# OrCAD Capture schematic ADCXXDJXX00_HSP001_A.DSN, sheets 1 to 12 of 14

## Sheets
1 PAGE01 - BLOCK DIAGRAM: title: BLOCK DIAGRAM; rev: A; note: HSP001
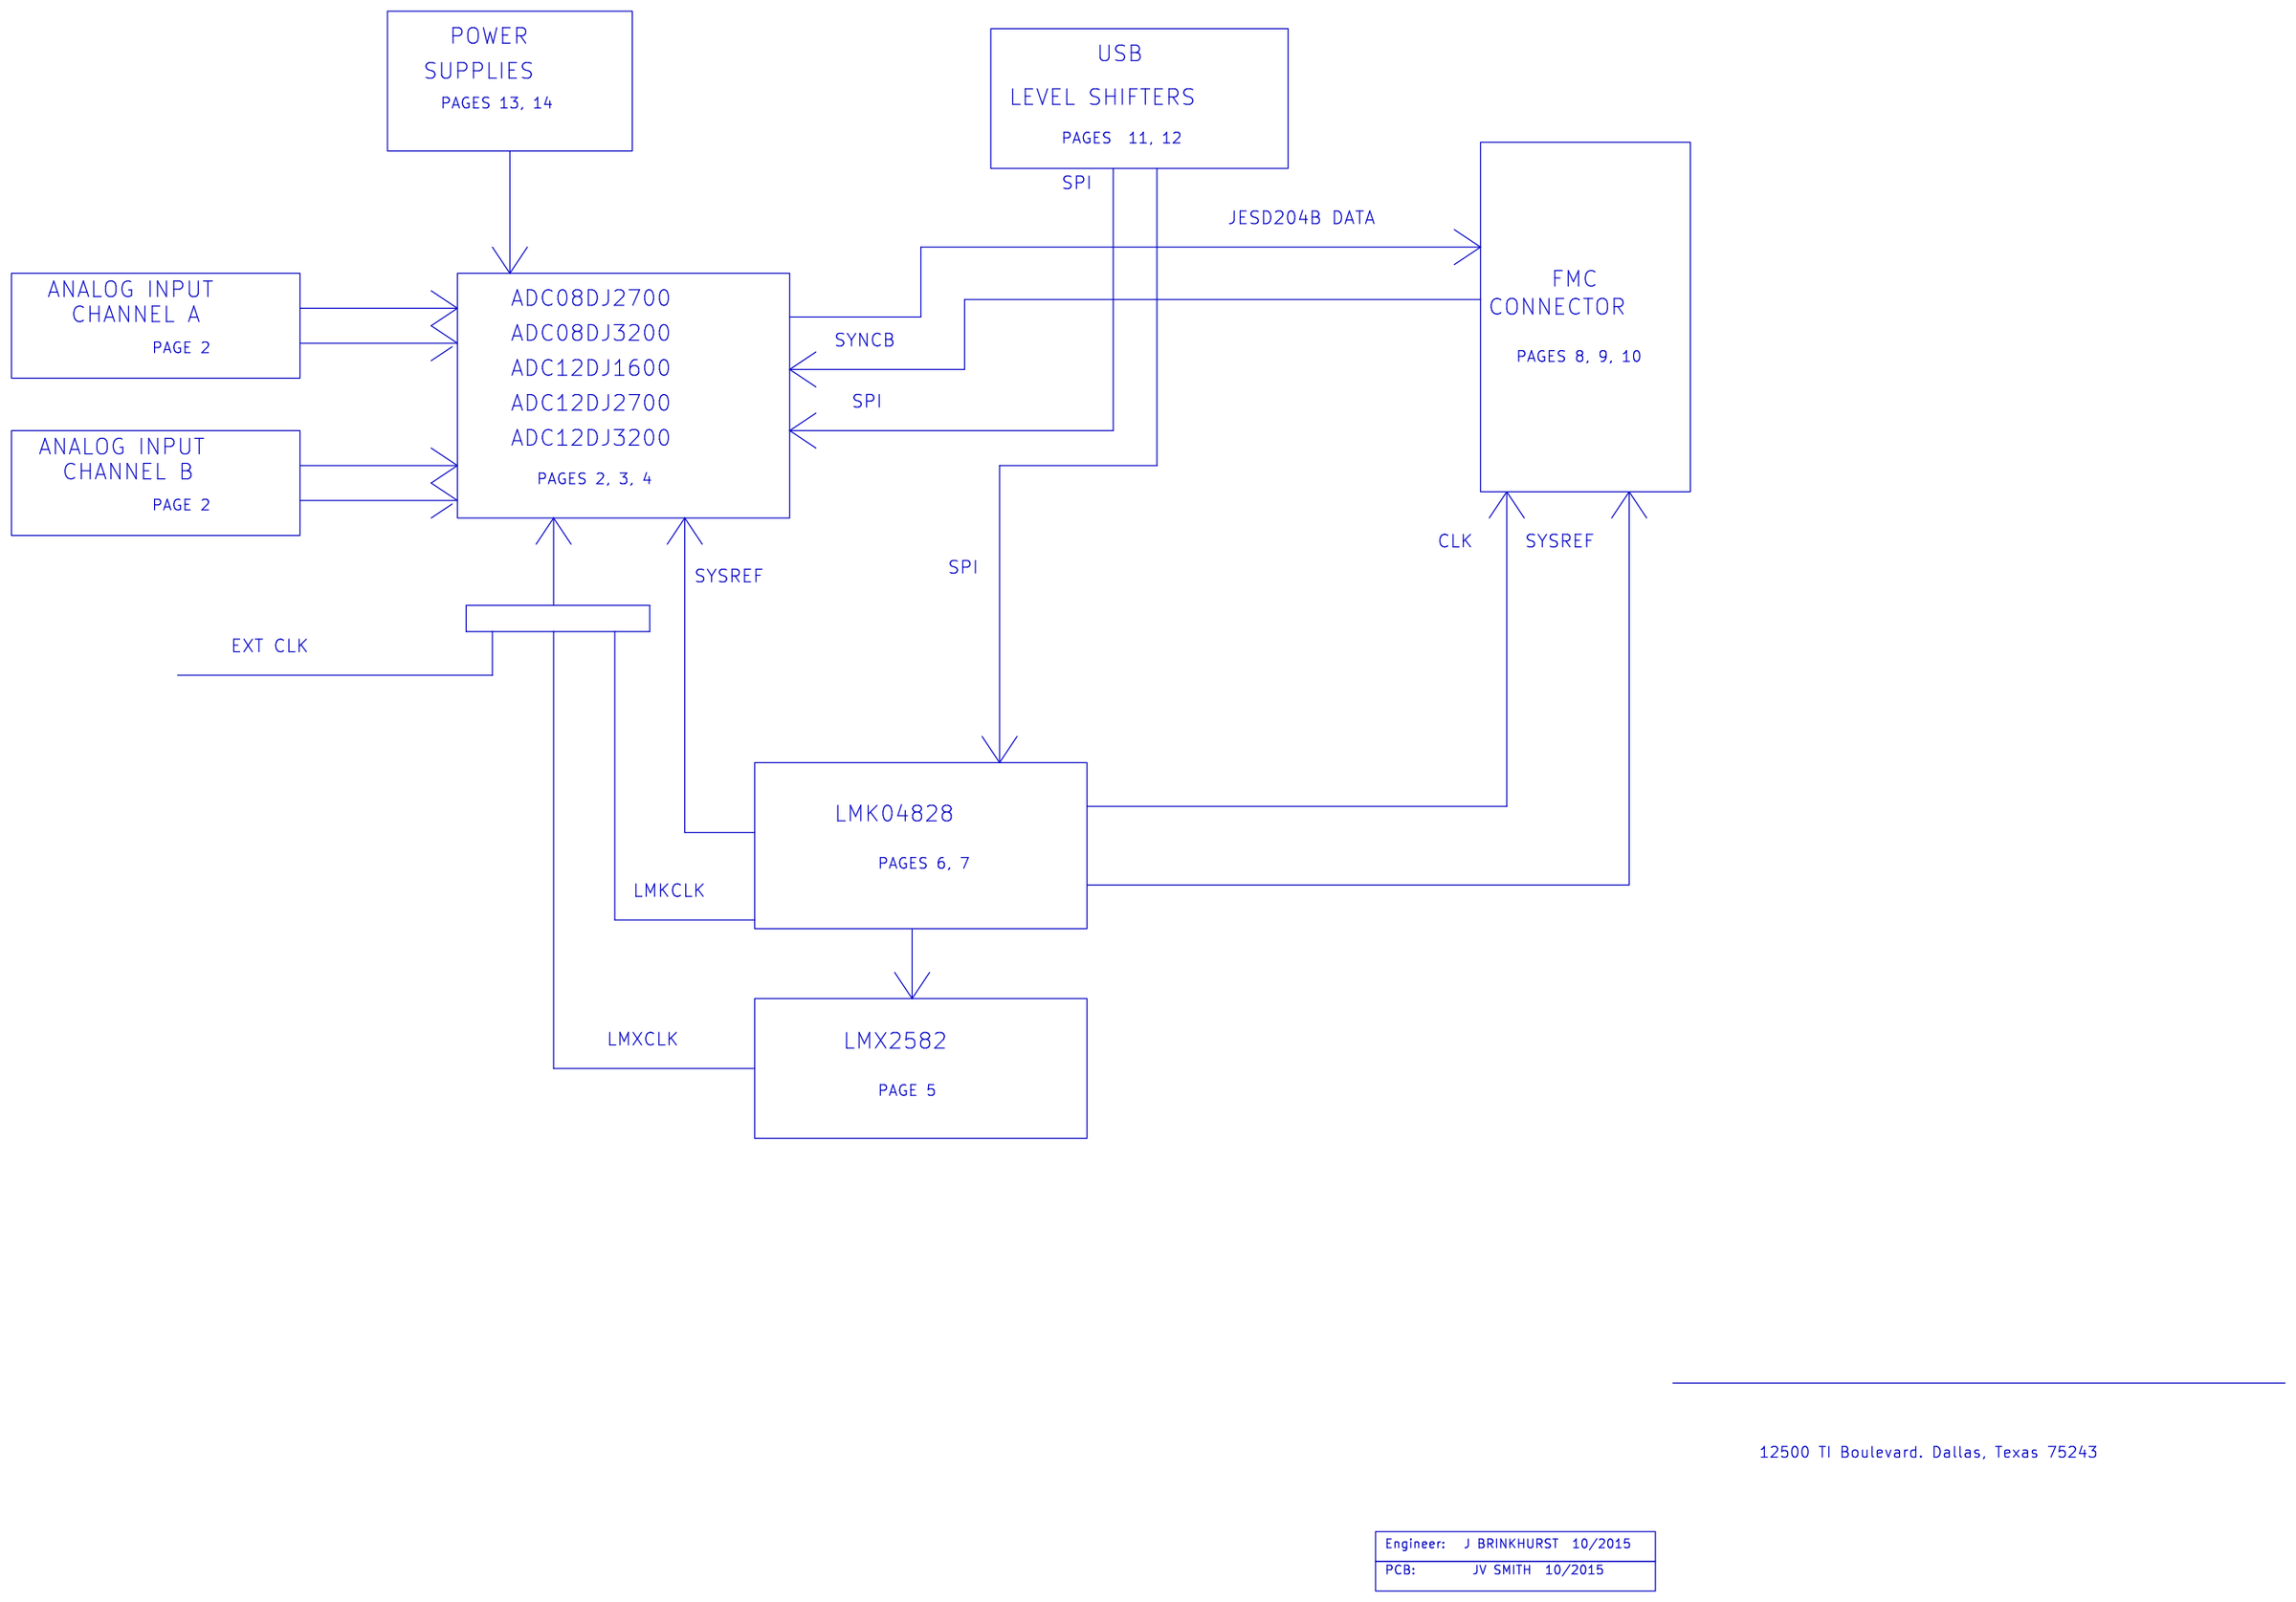
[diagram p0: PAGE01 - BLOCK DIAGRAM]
2 PAGE02 - ADC ANALOG INPUT: size B; title: ANALOG IN
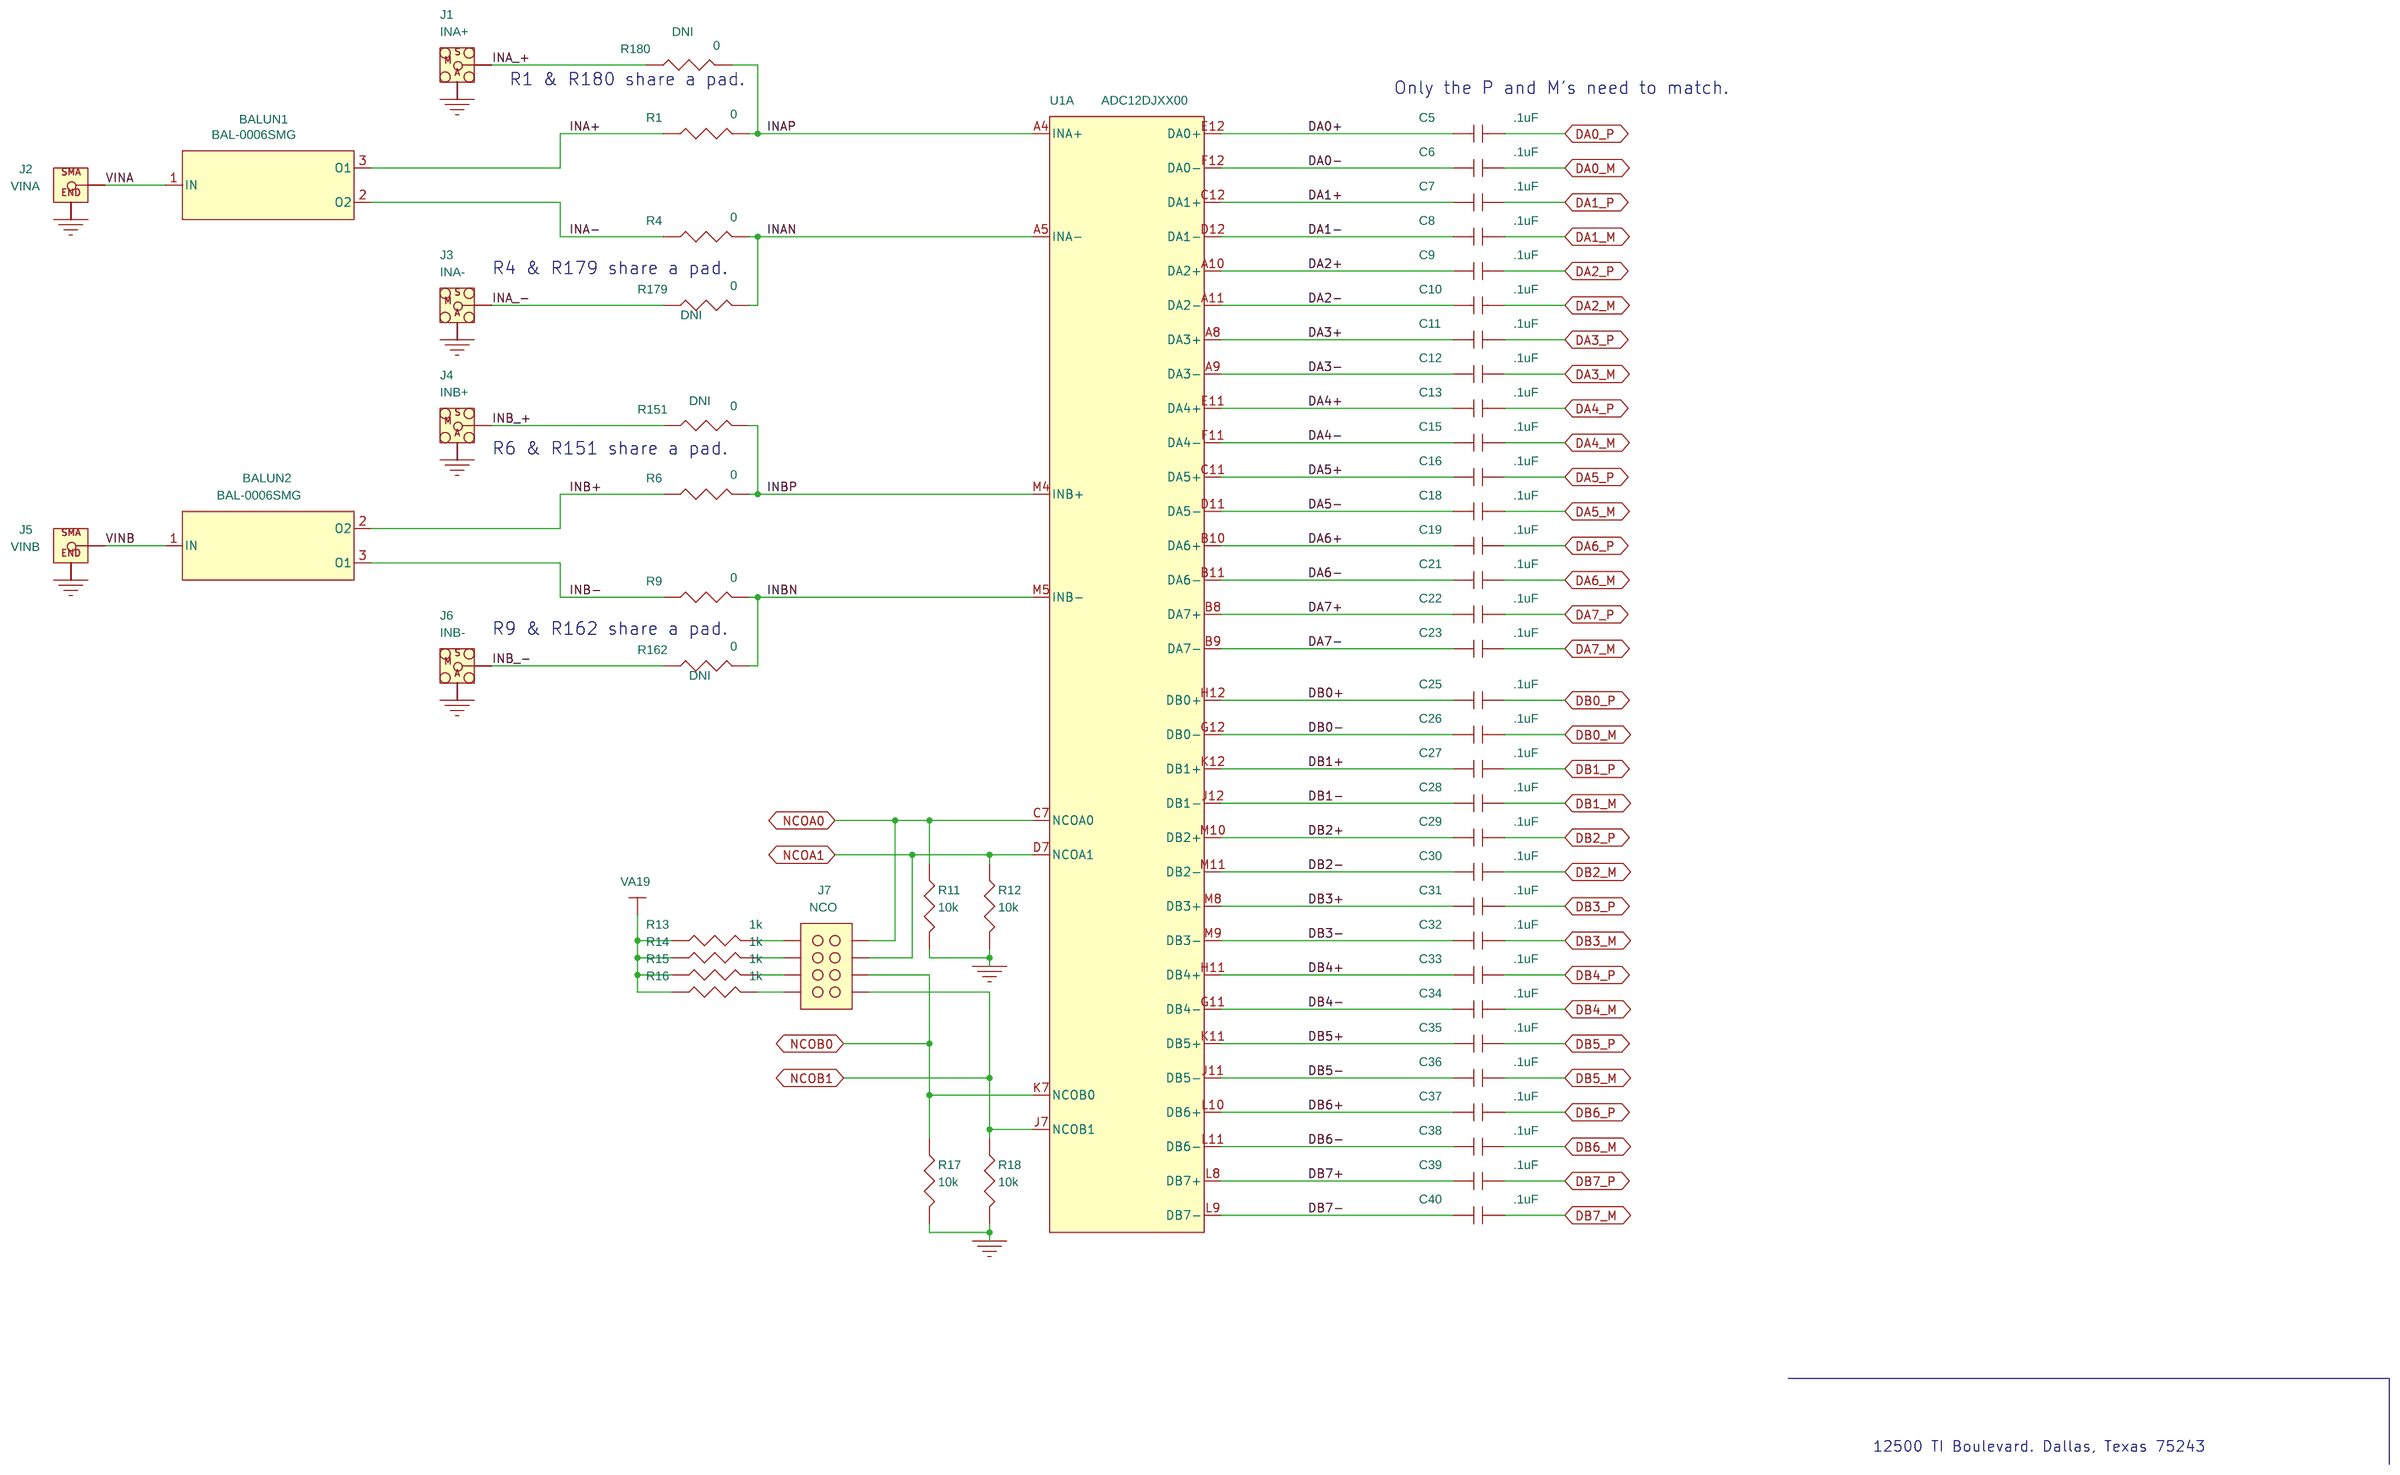
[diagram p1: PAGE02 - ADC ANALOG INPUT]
3 PAGE03 - ADC SPI: size B; title: ADC
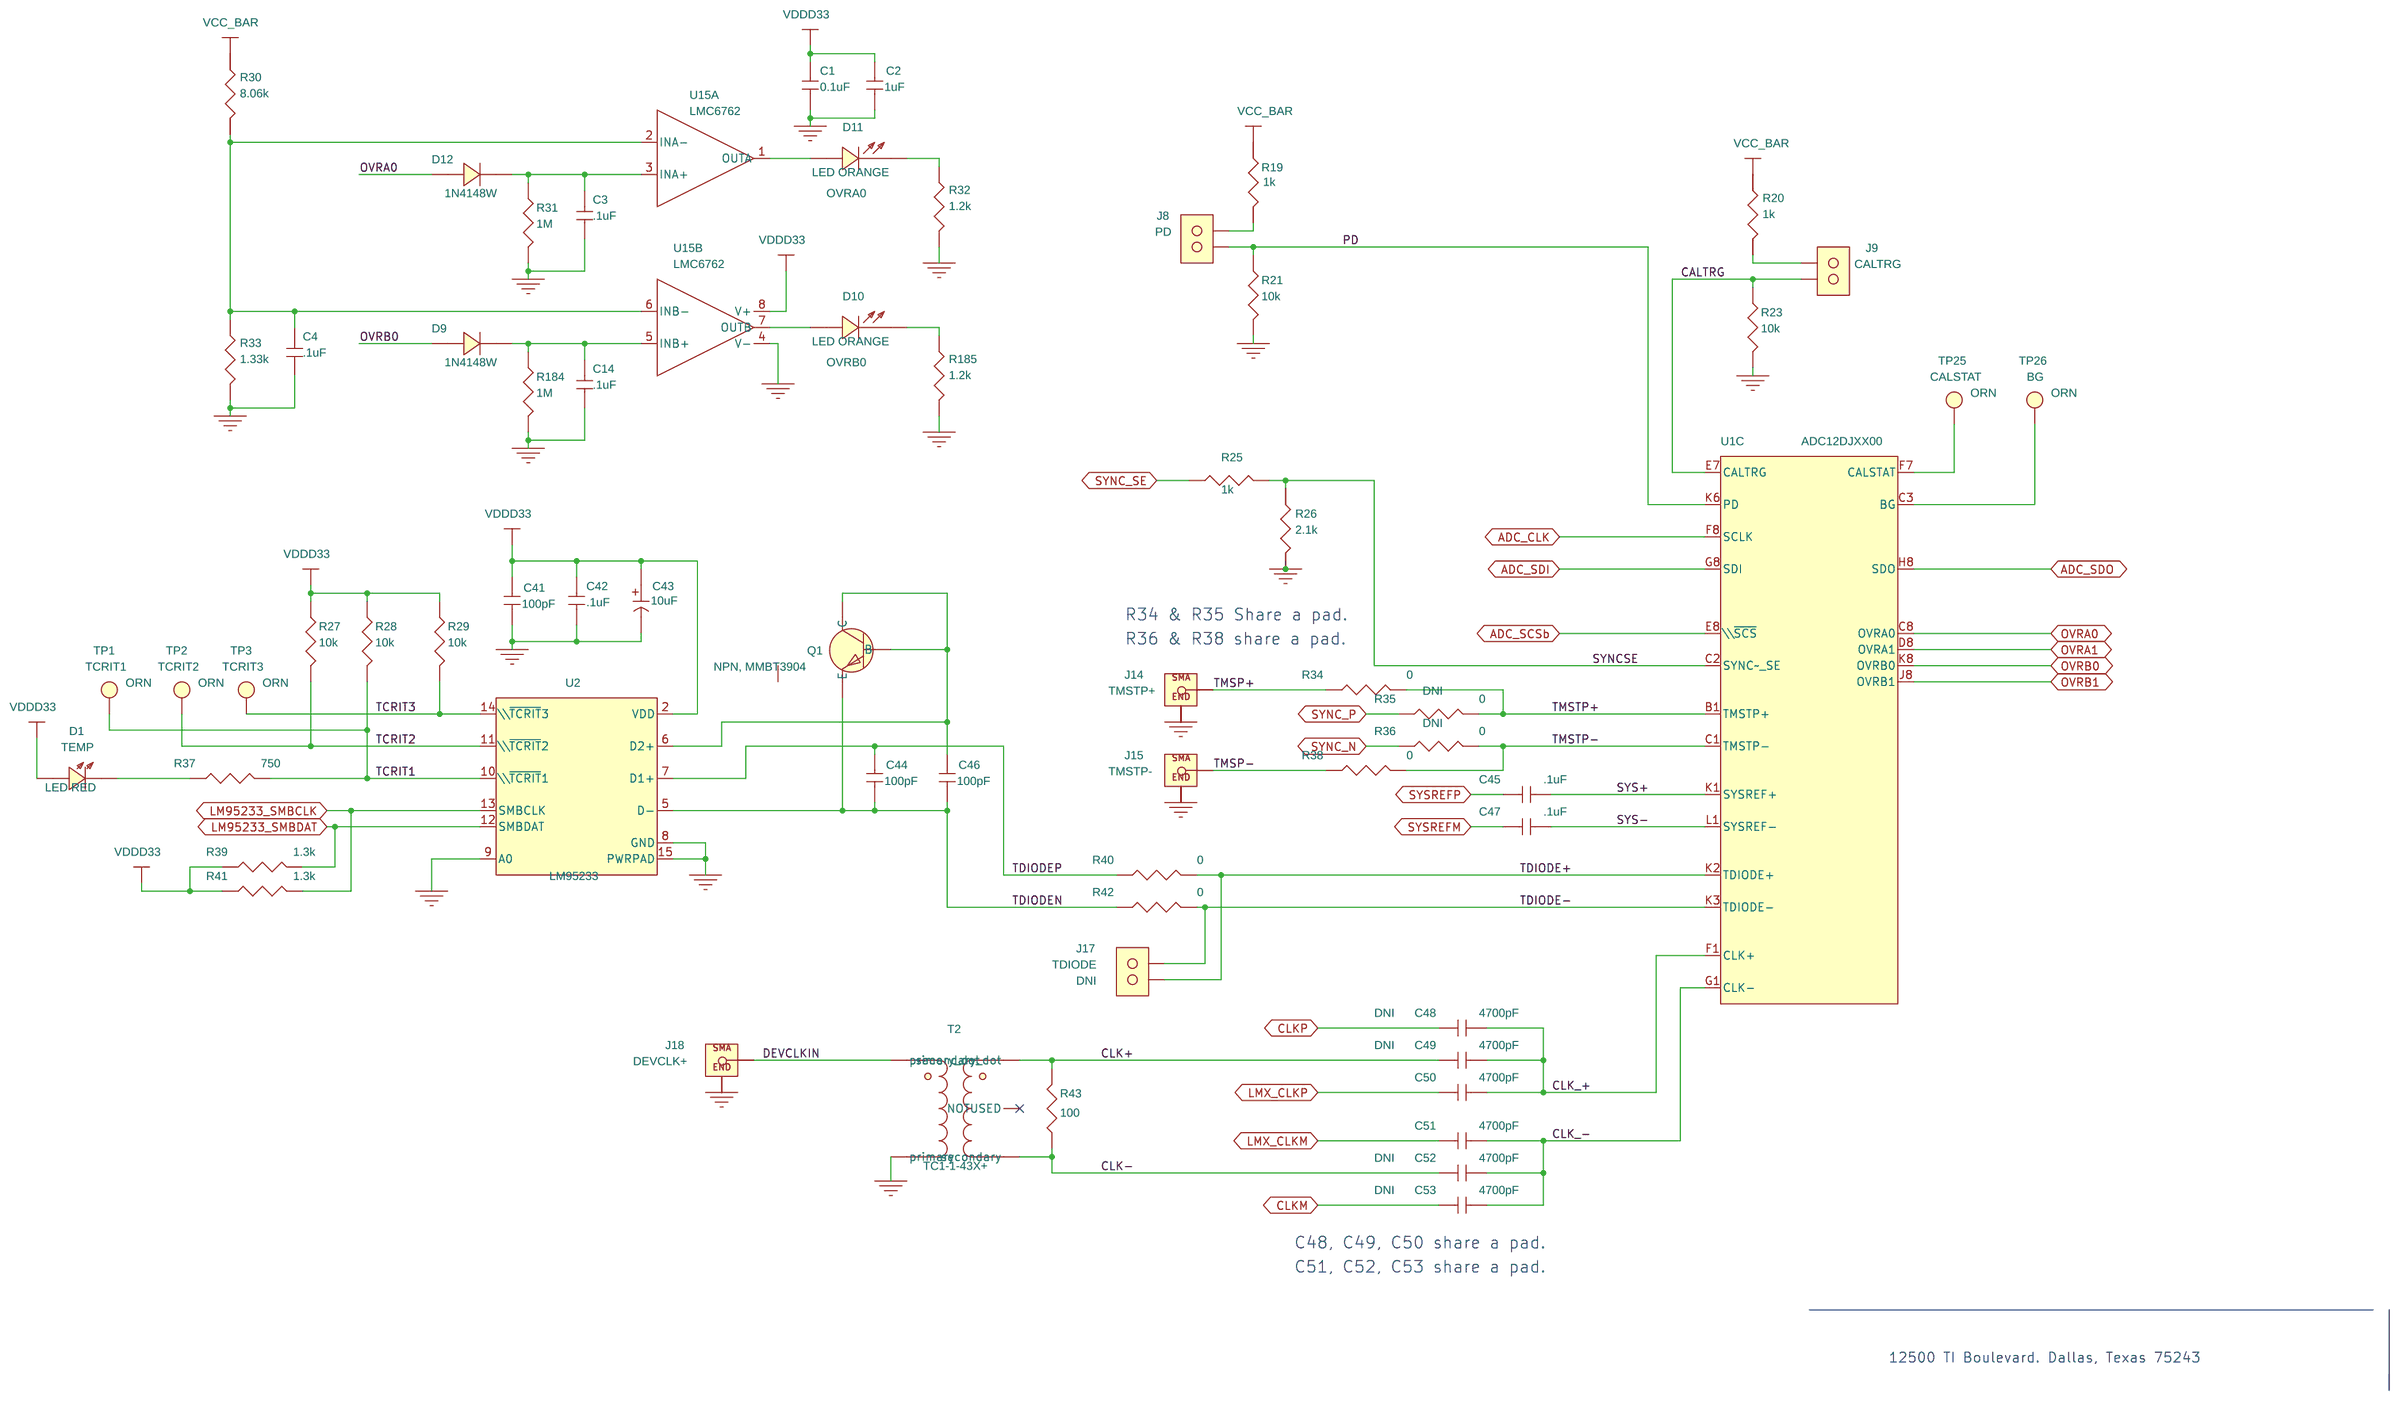
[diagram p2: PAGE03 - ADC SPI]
4 PAGE04 - ADC PWR: size B; title: ADC  POWER
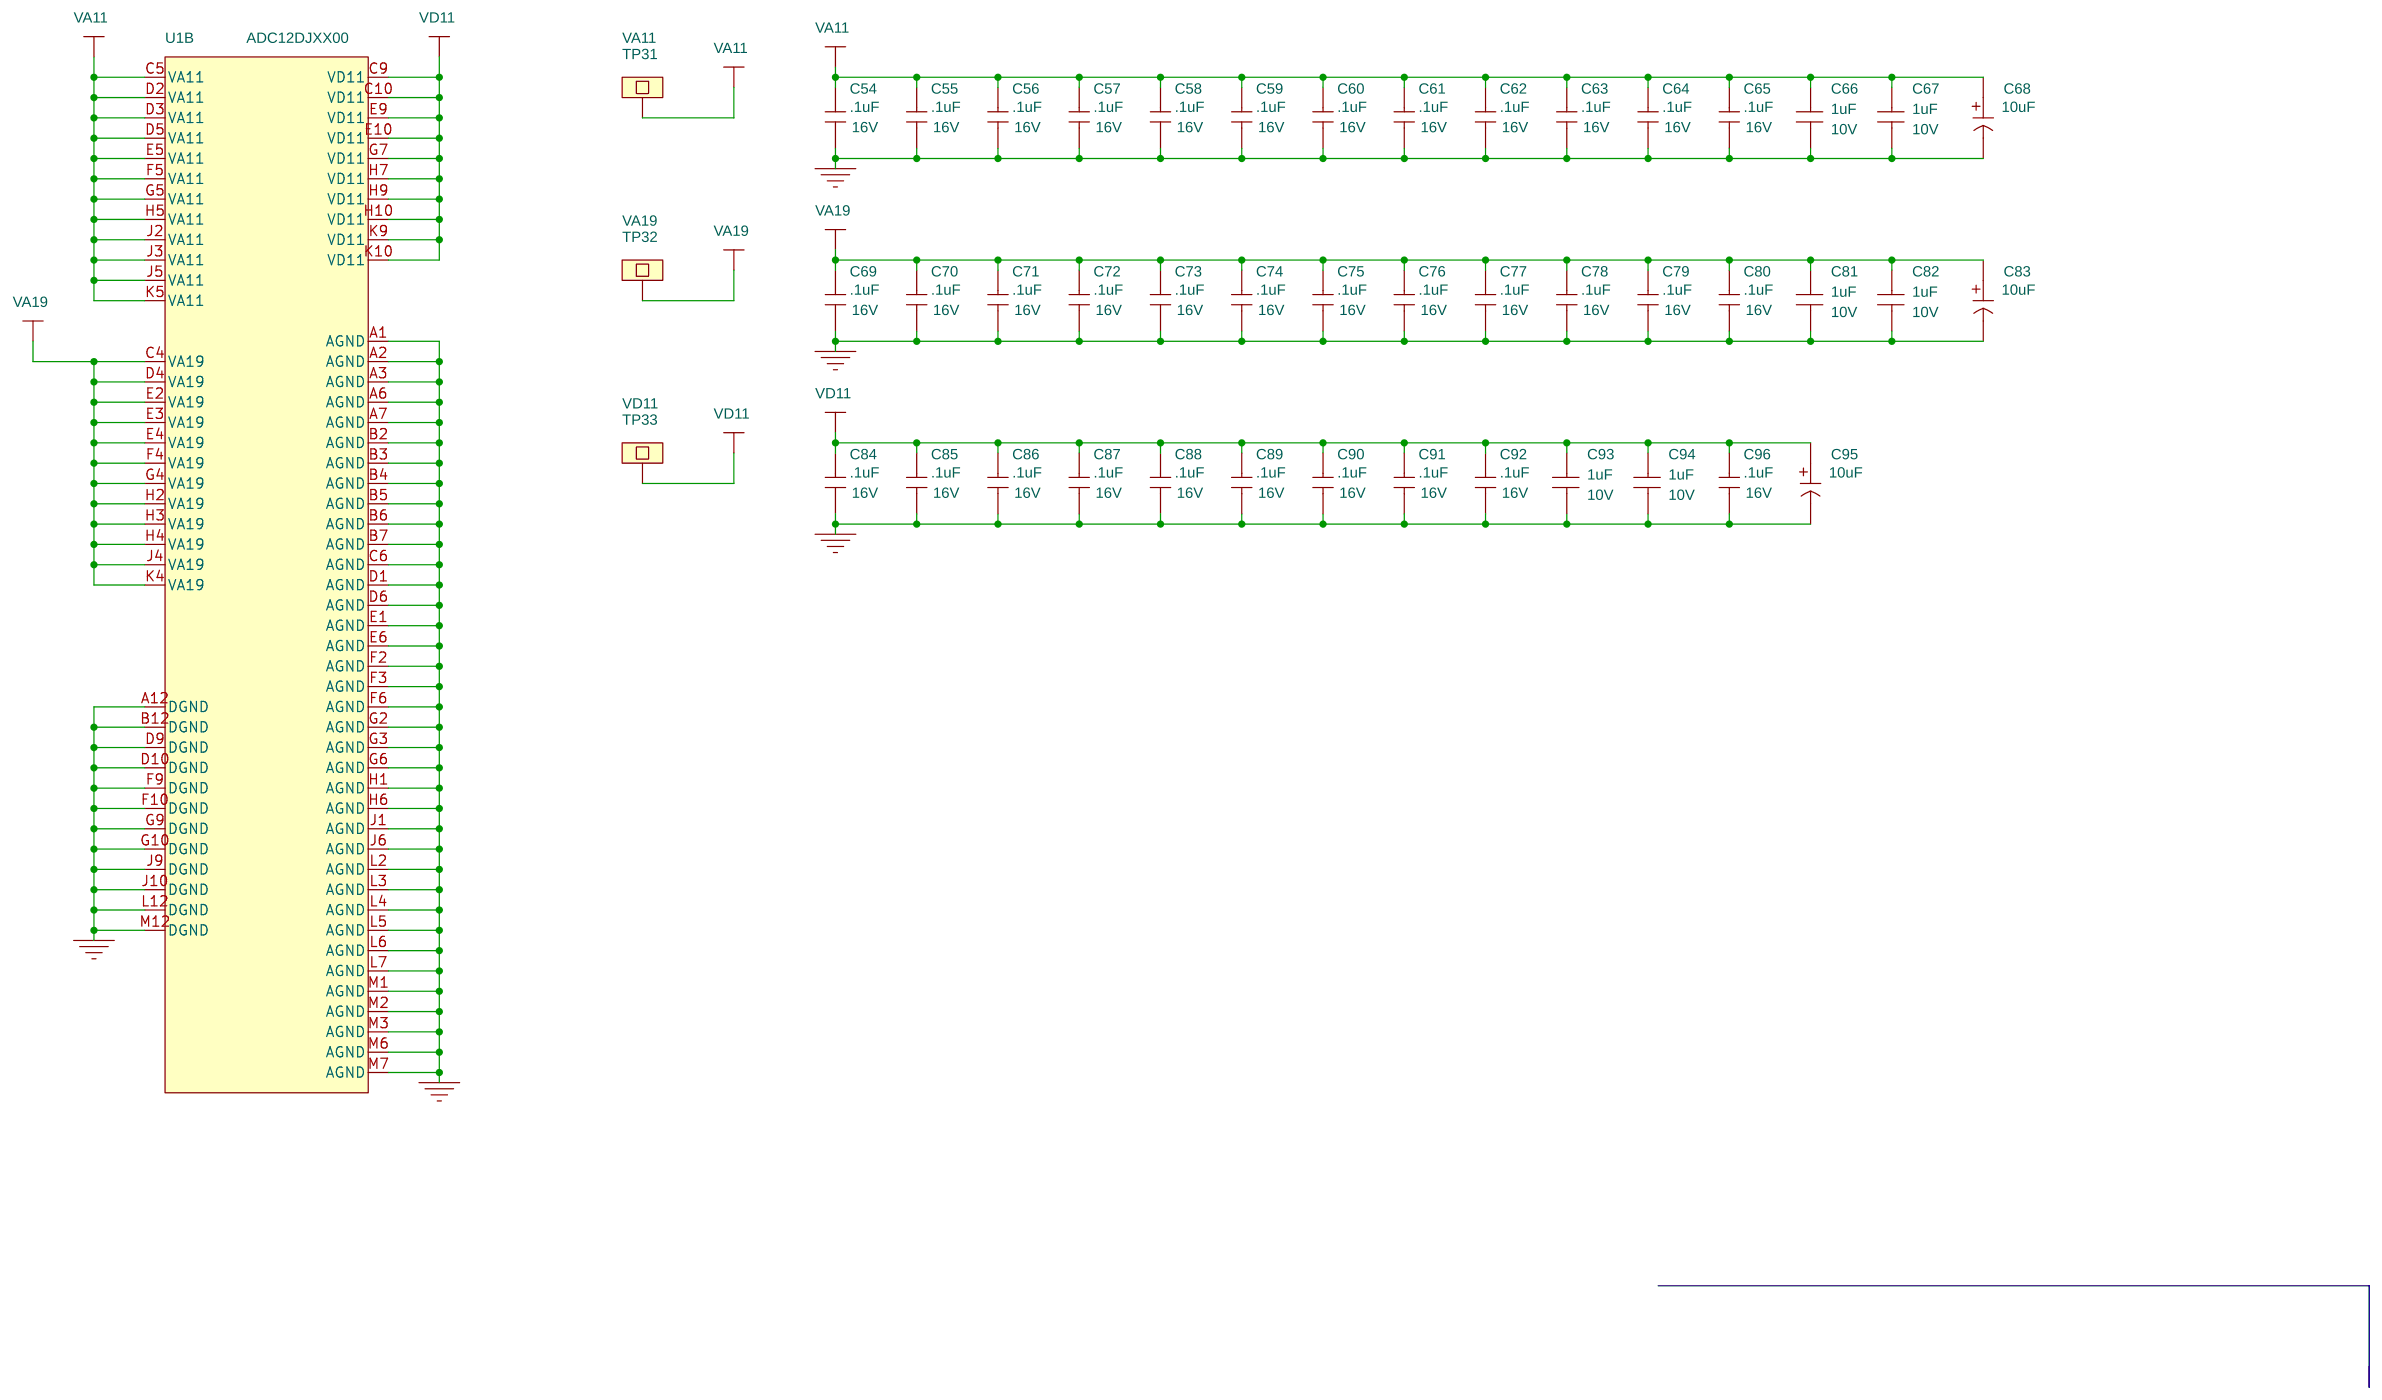
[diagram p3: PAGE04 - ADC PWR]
5 PAGE05 - LMX: size B; title: LMX
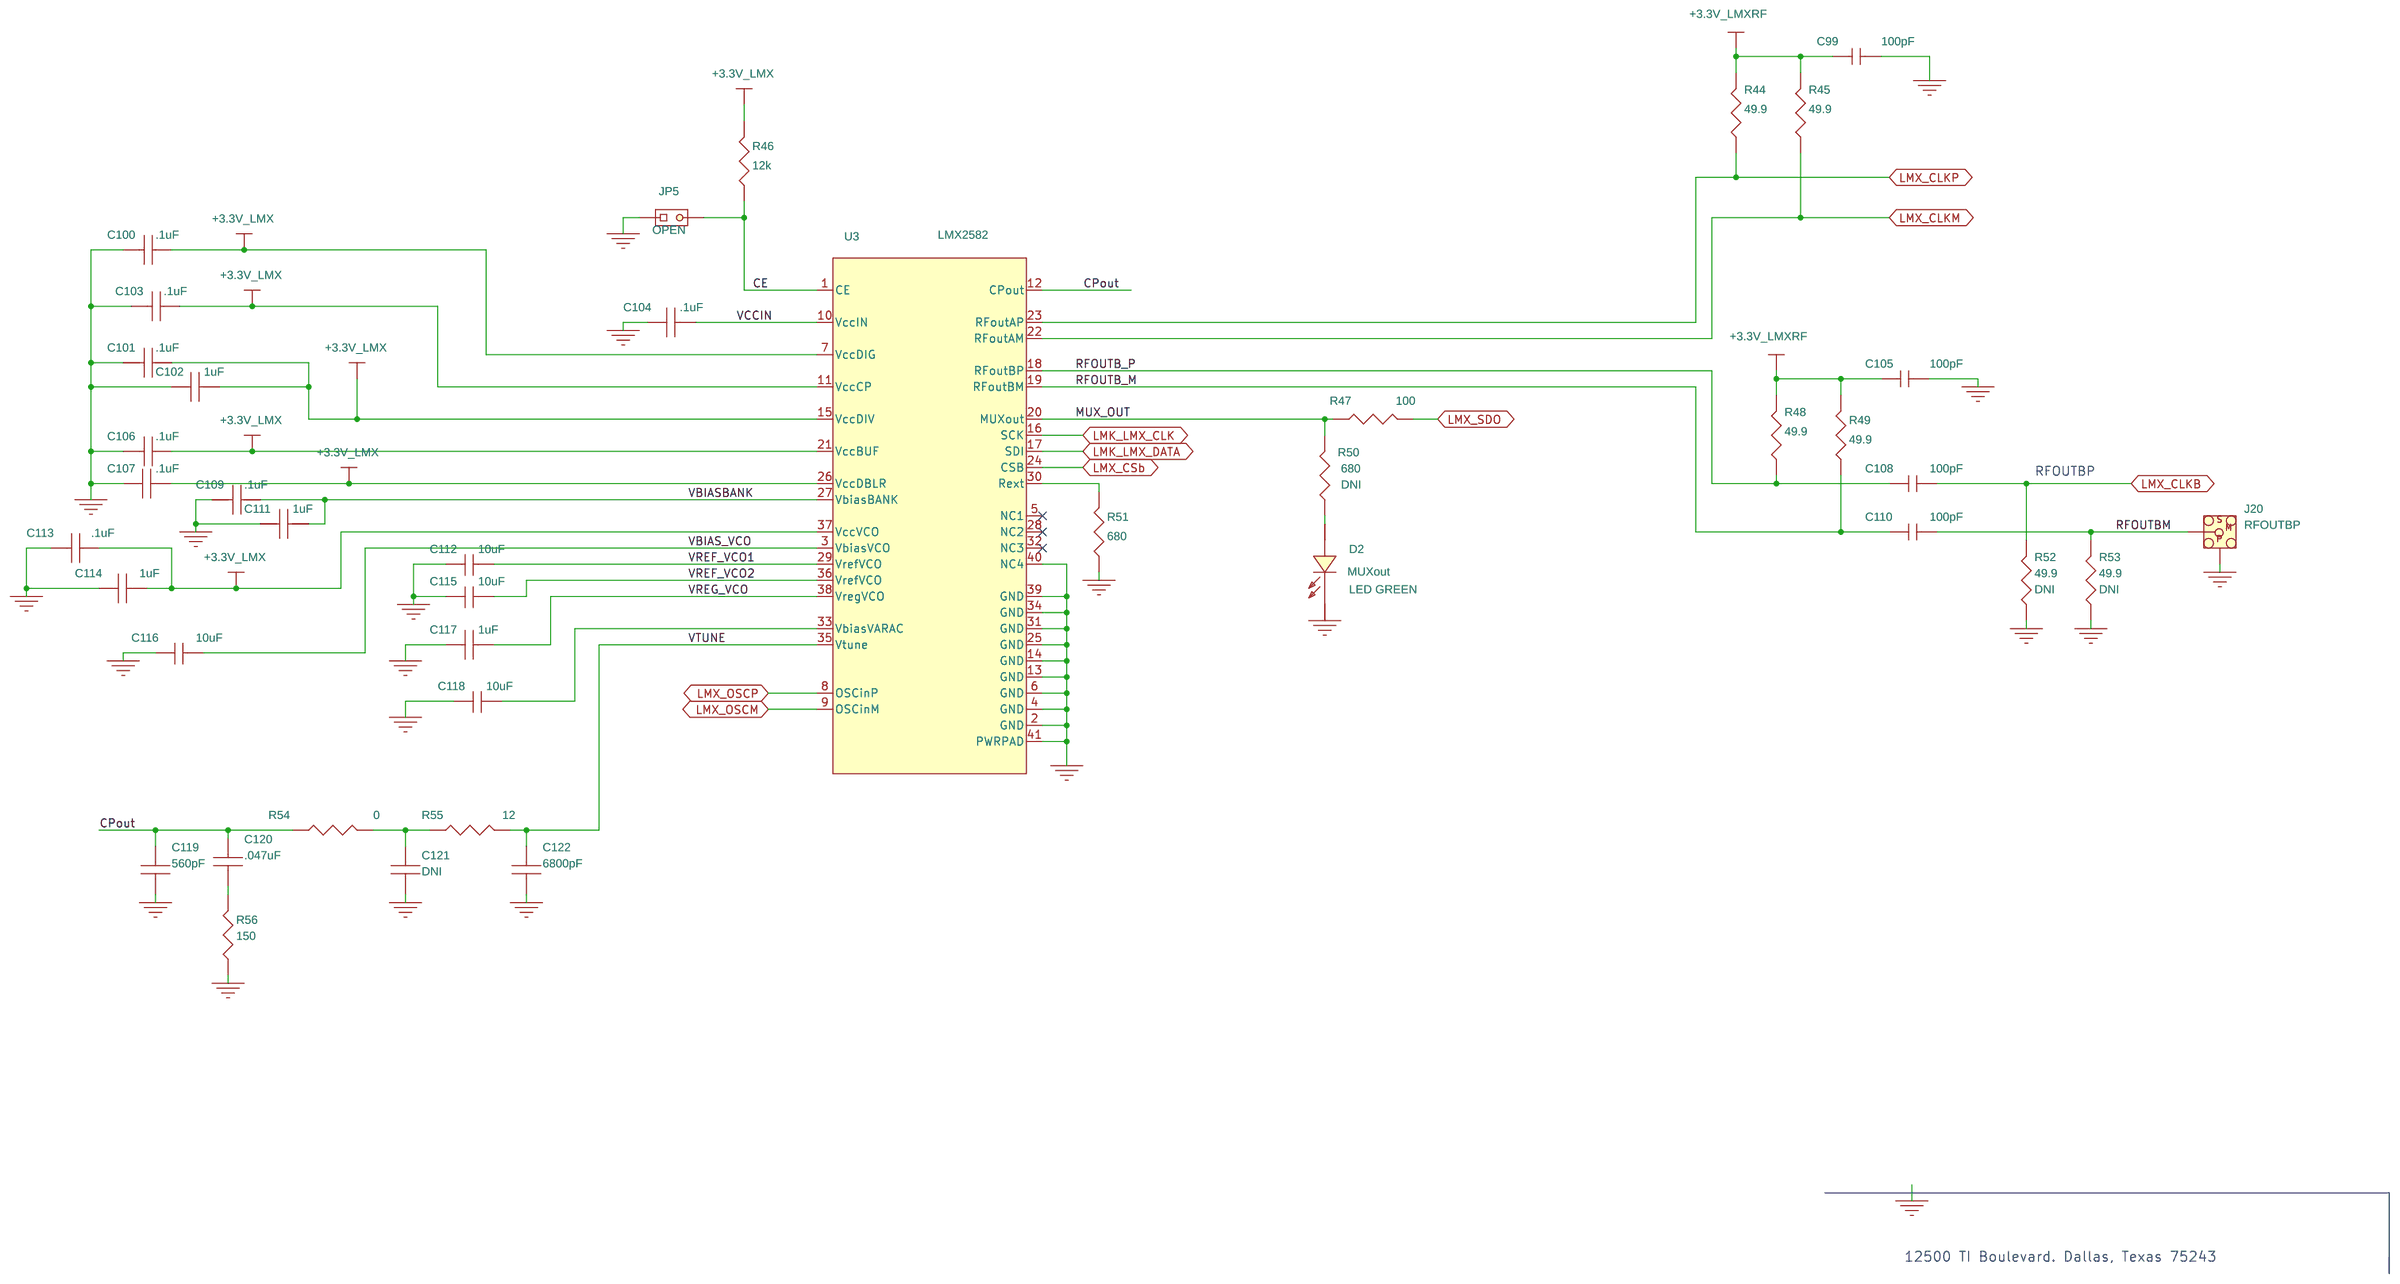
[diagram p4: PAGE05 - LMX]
6 PAGE06 - LMK: size B; title: LMK
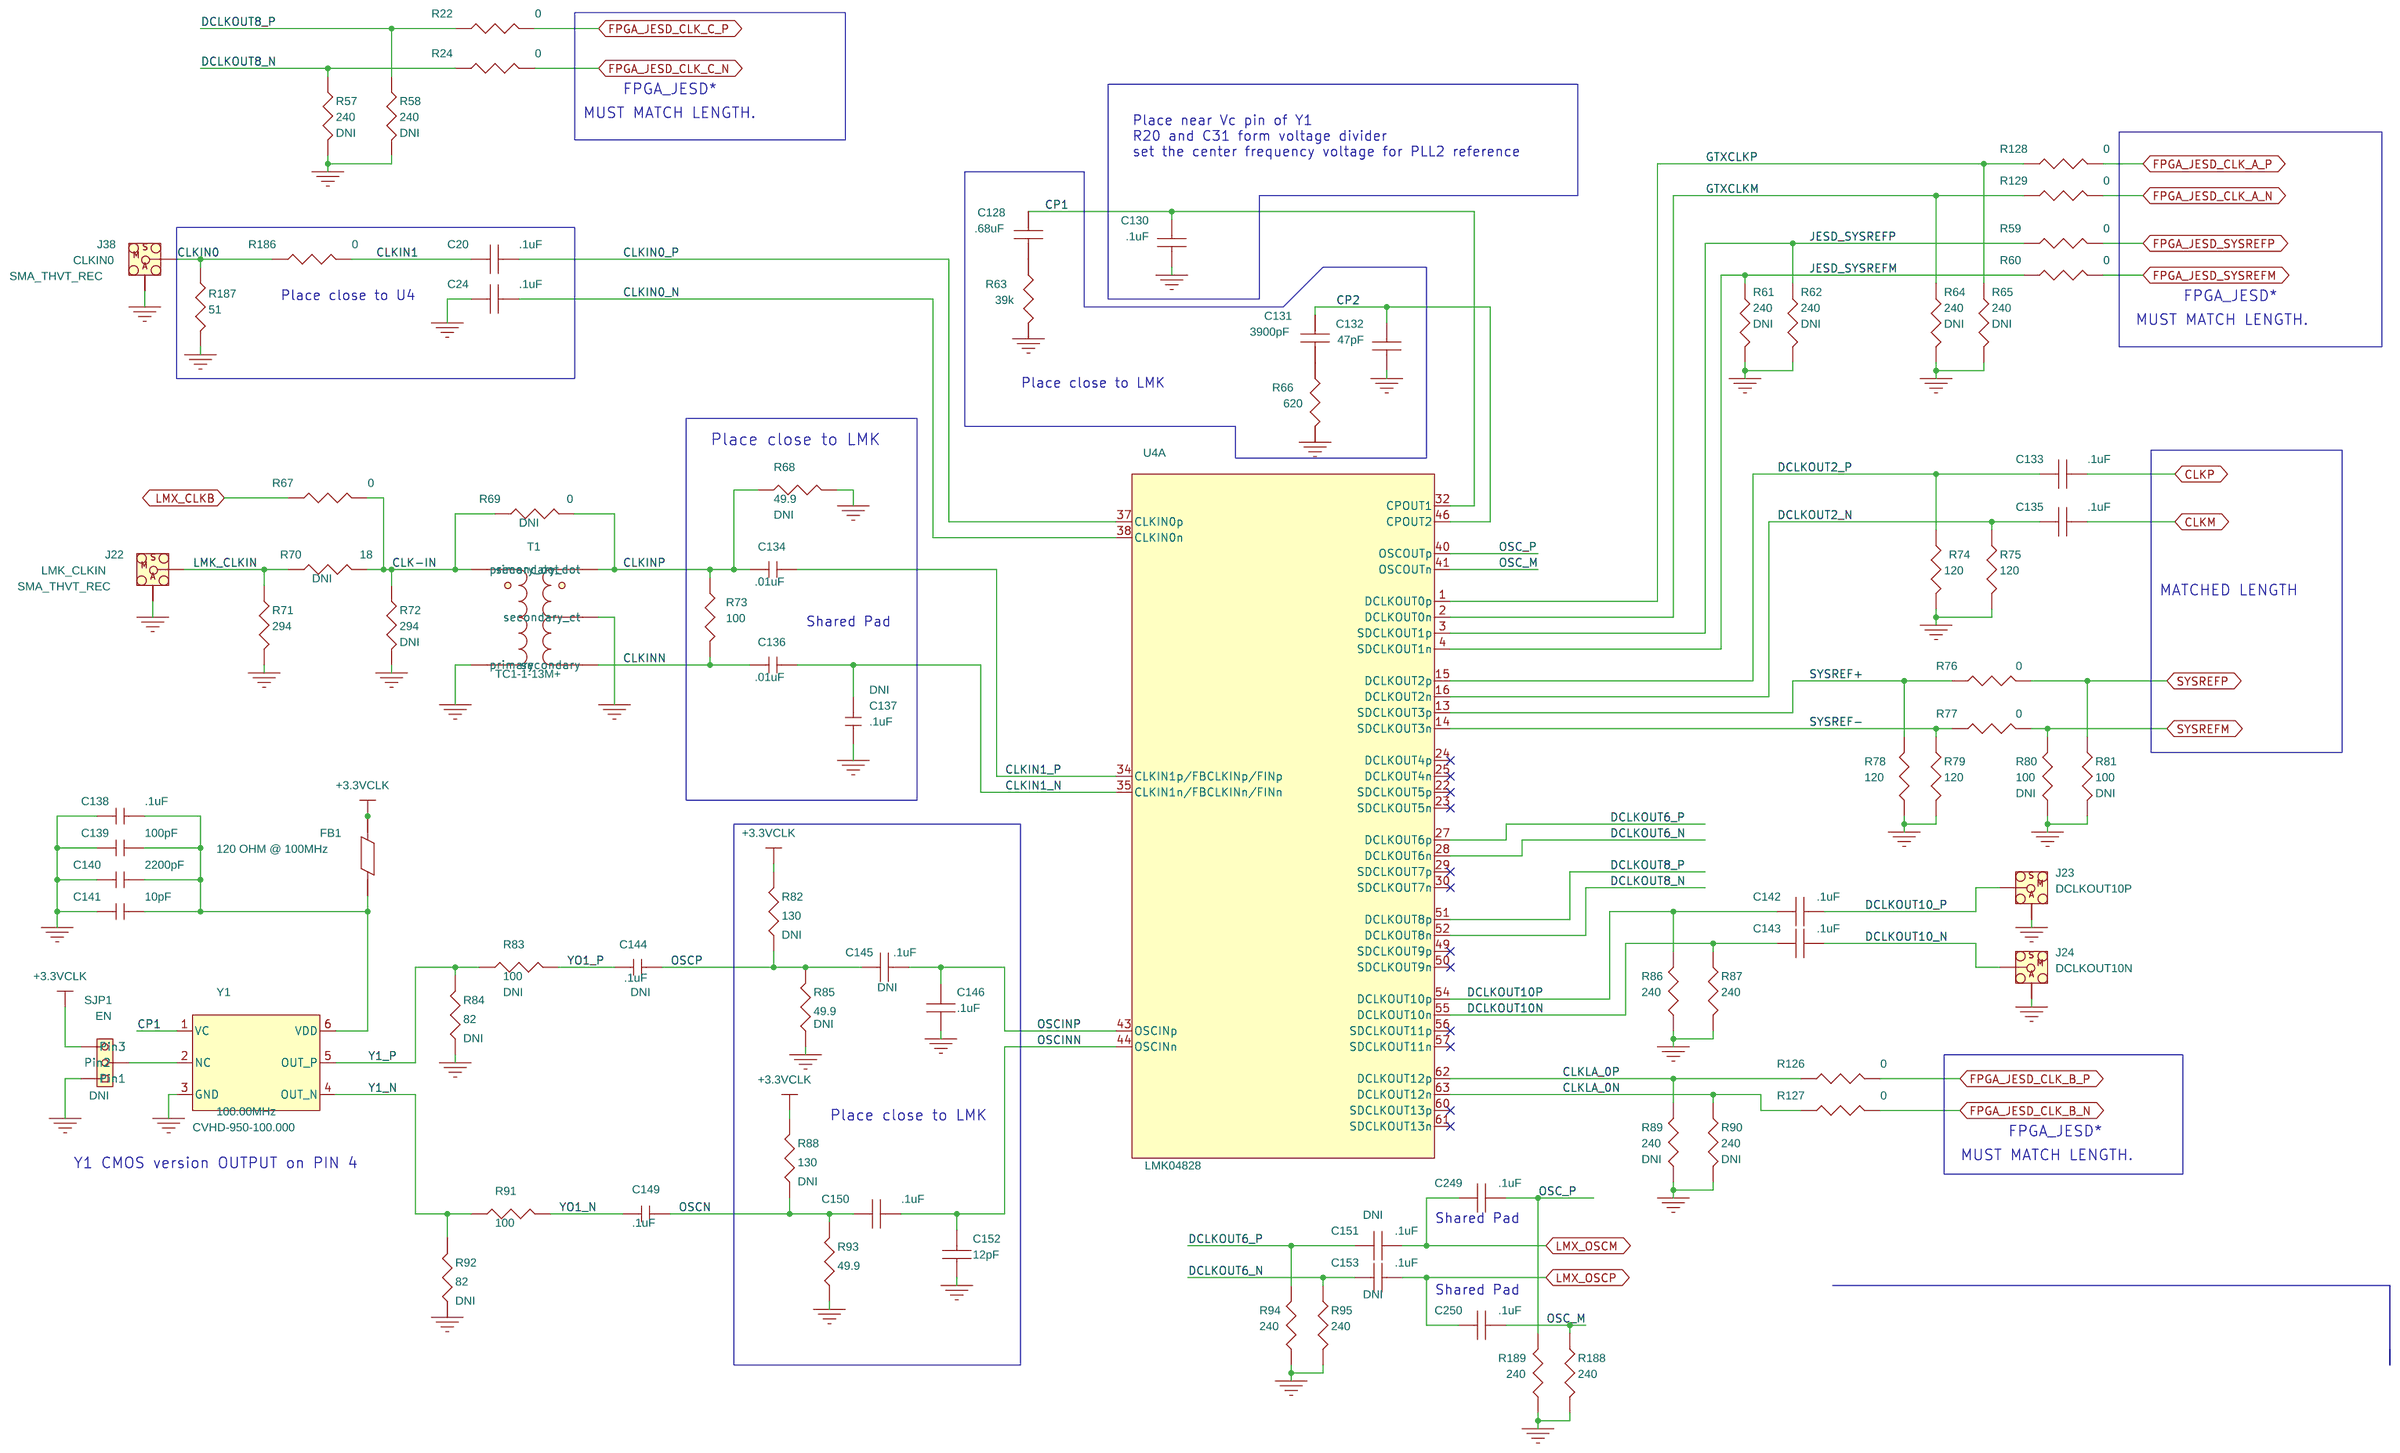
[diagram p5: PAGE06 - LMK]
7 PAGE07 - LMK POWER: size B; title: LMK POWER
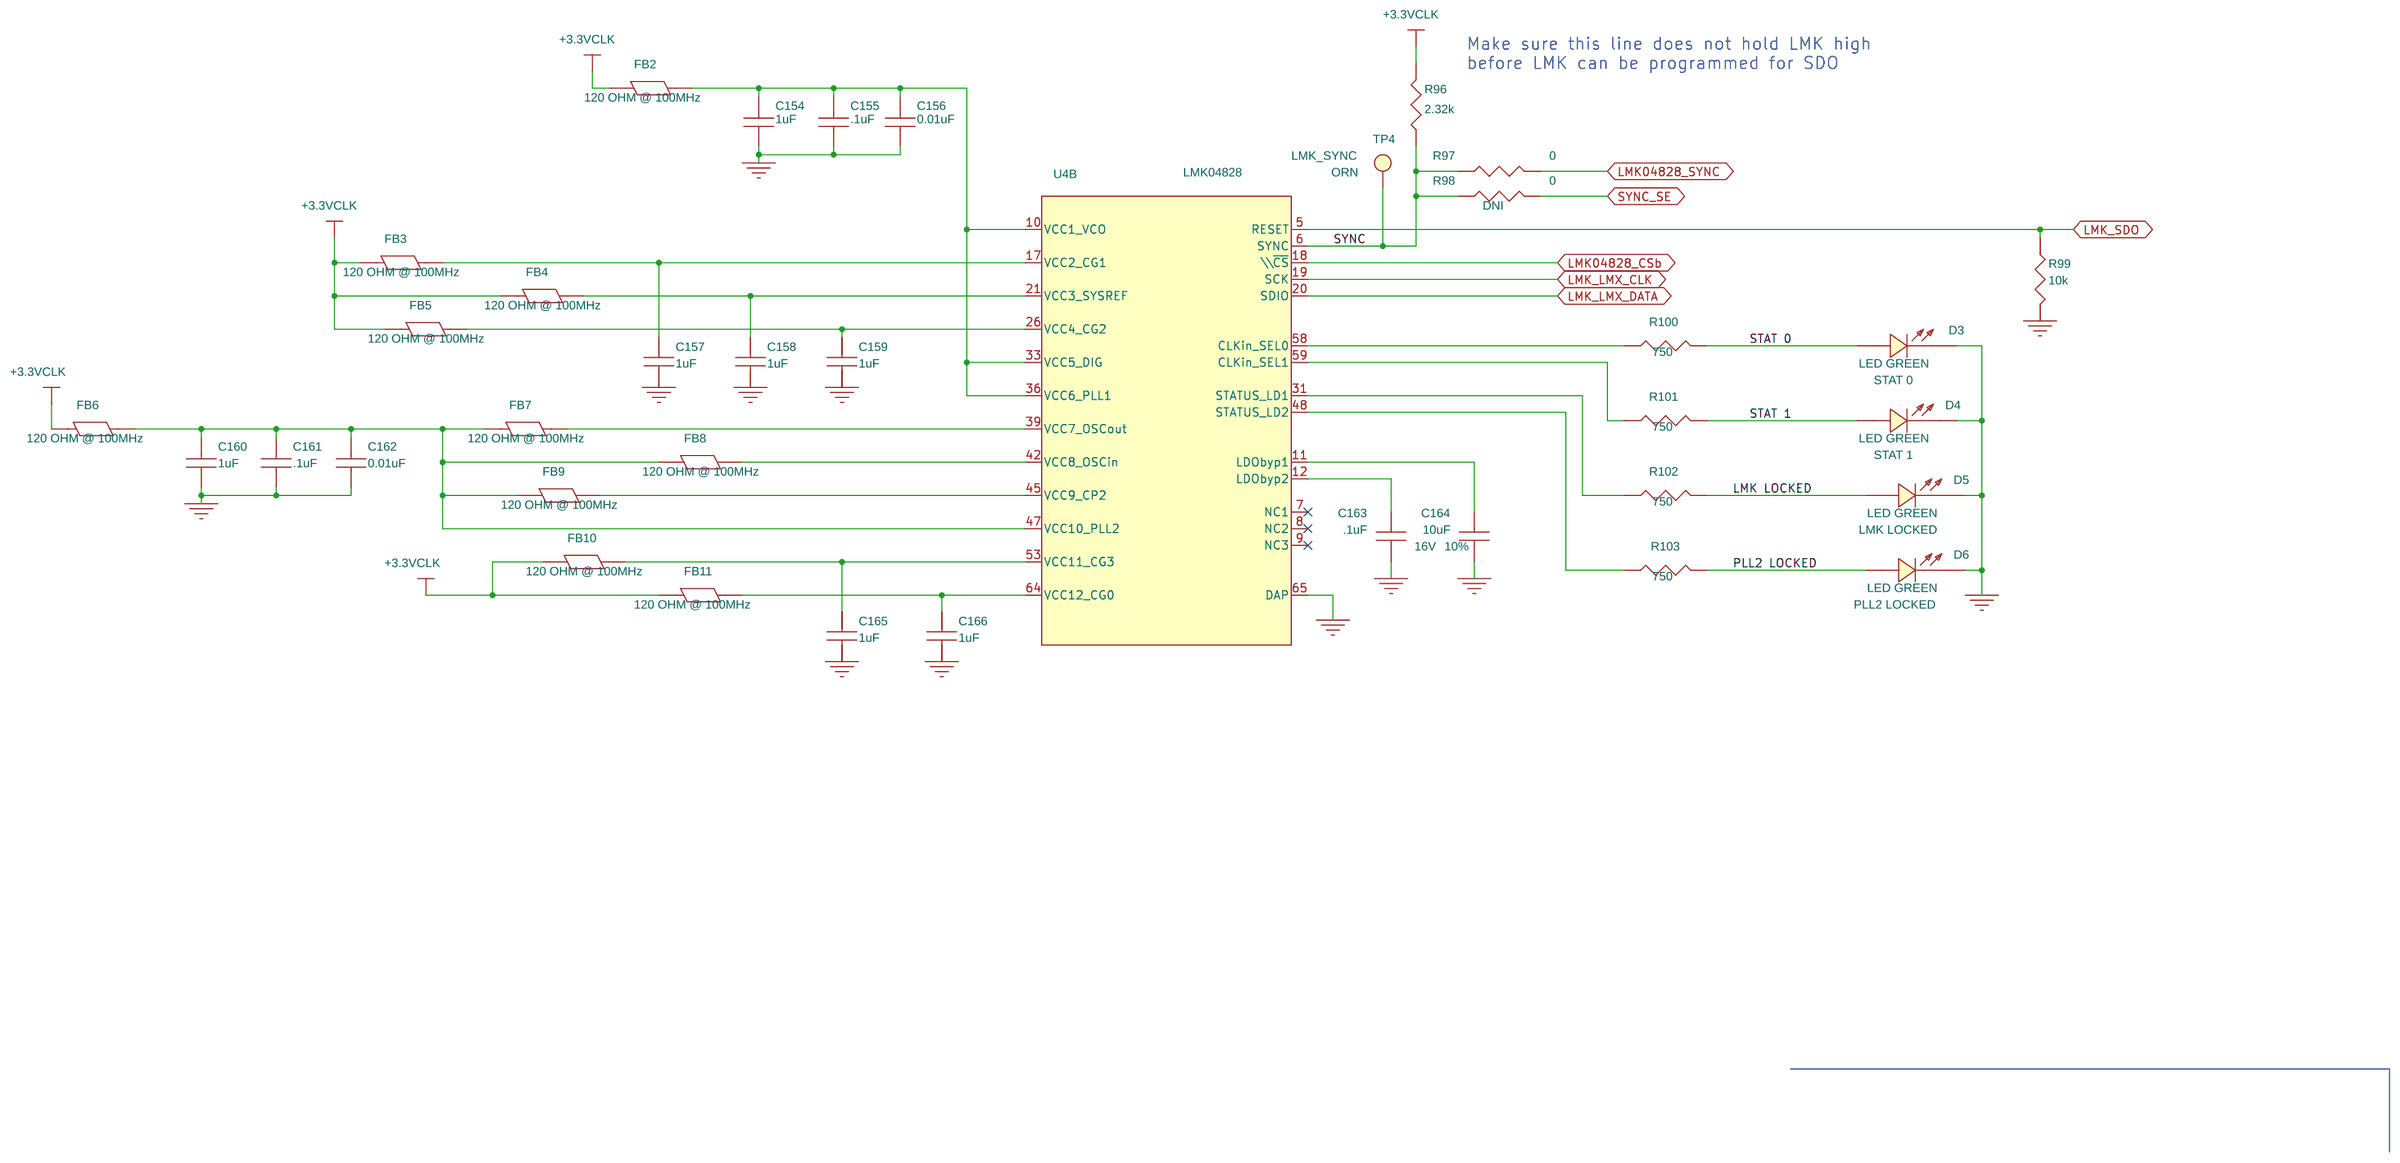
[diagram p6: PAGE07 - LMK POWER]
8 PAGE08 - OUTPUT FMC CONN: size B; title: OUTPUT - FMC CONNECTOR
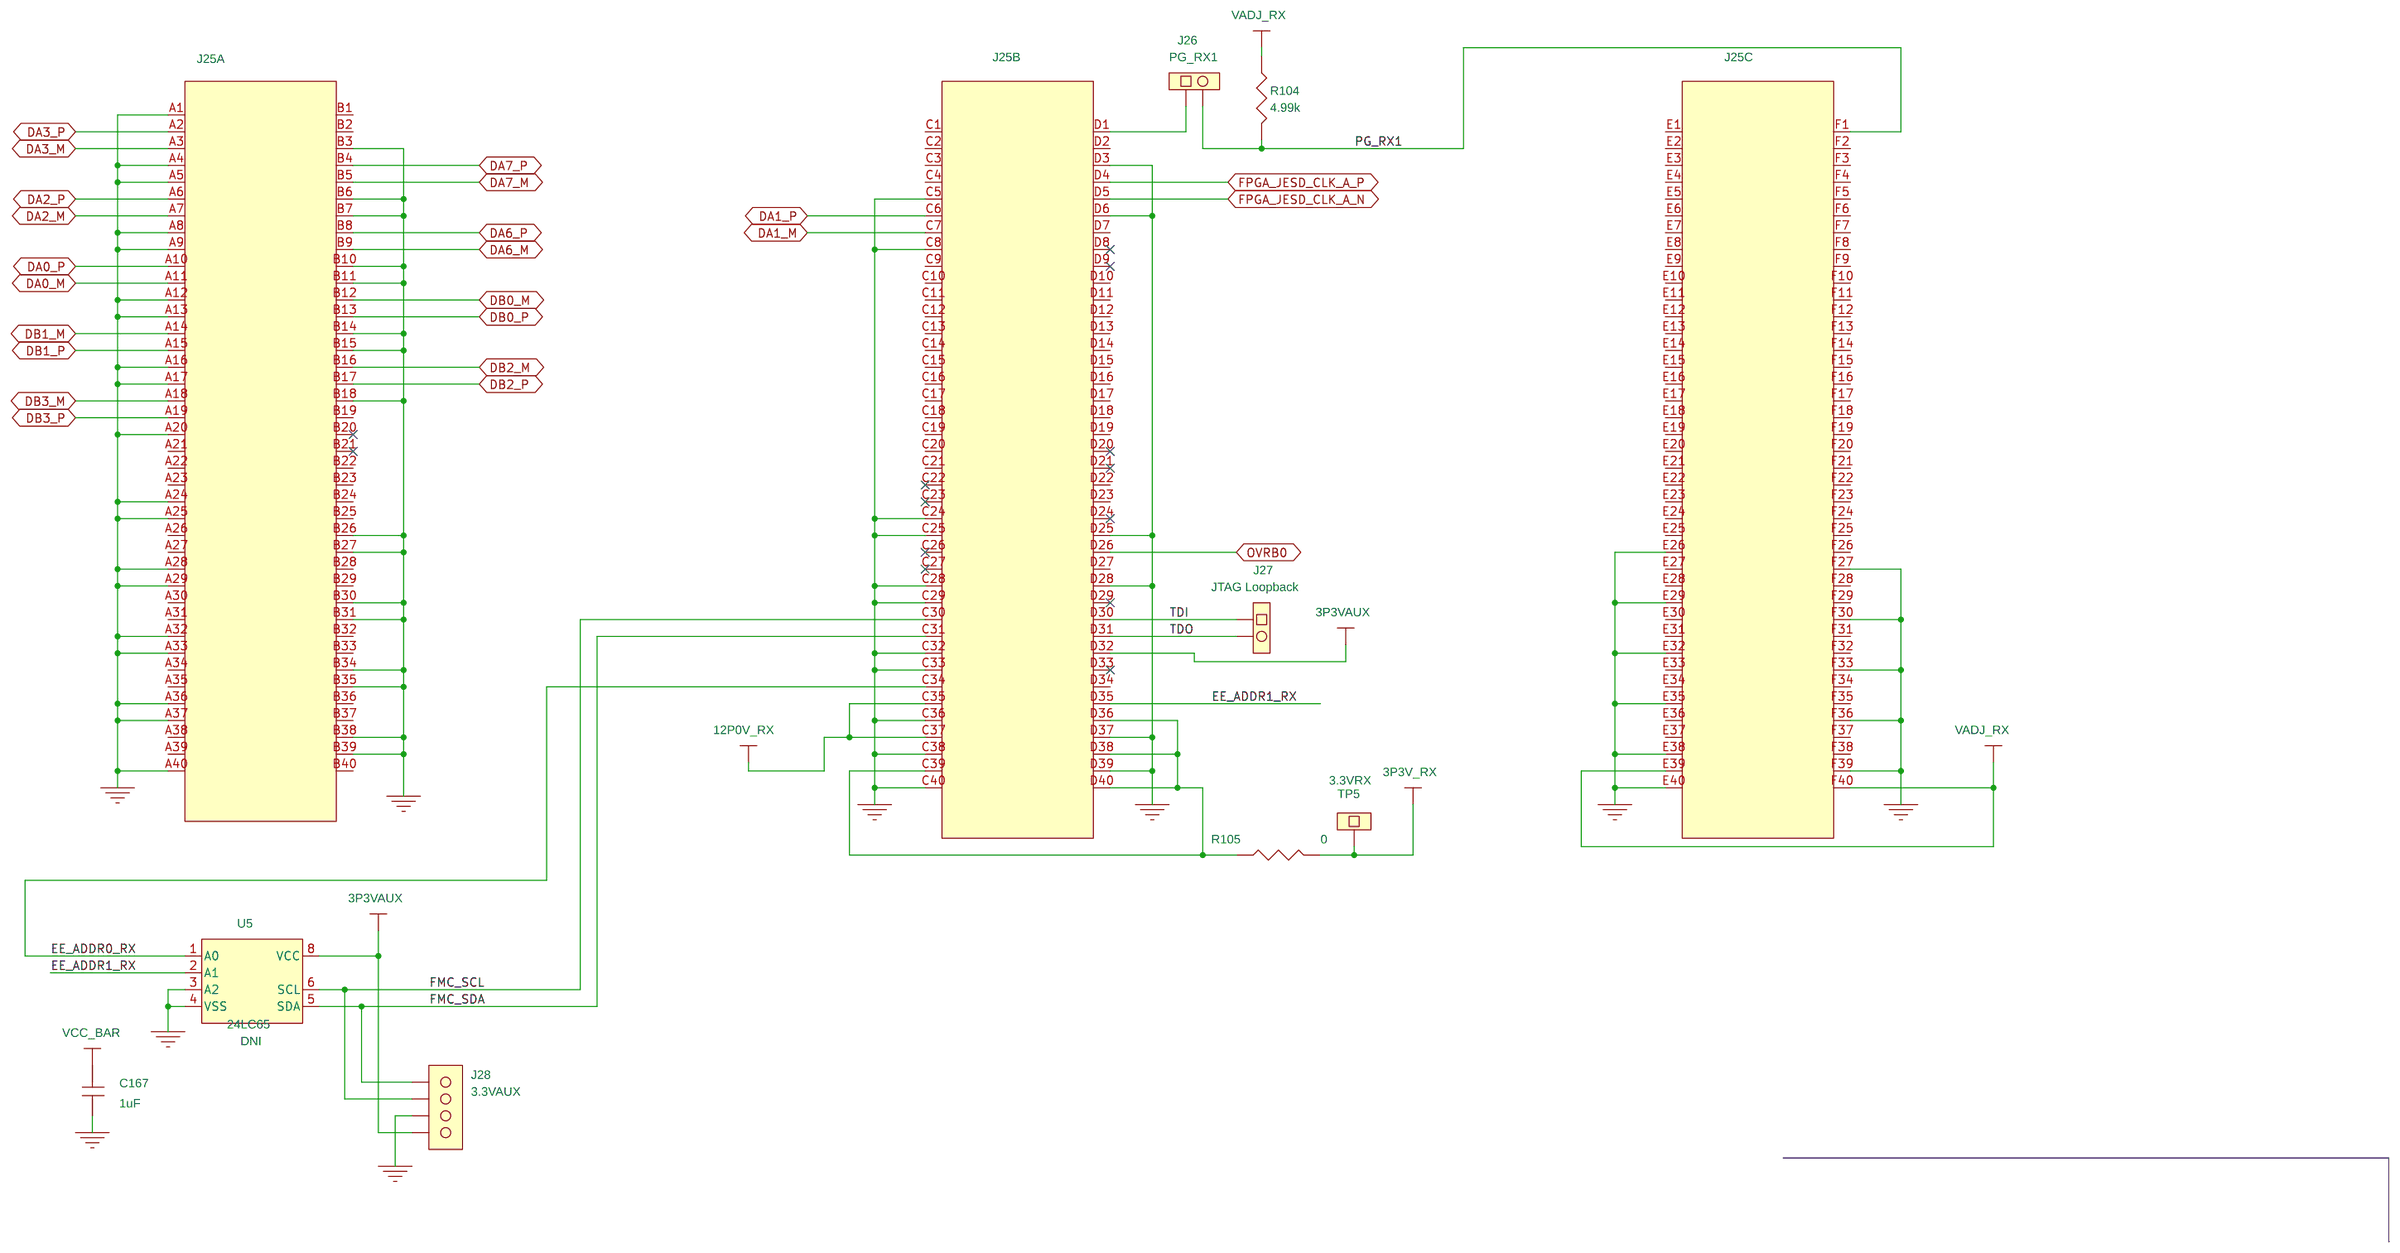
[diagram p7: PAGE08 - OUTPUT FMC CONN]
9 PAGE09 - OUTPUT FMC CONN: size B; title: OUTPUT - FMC CONNECTOR
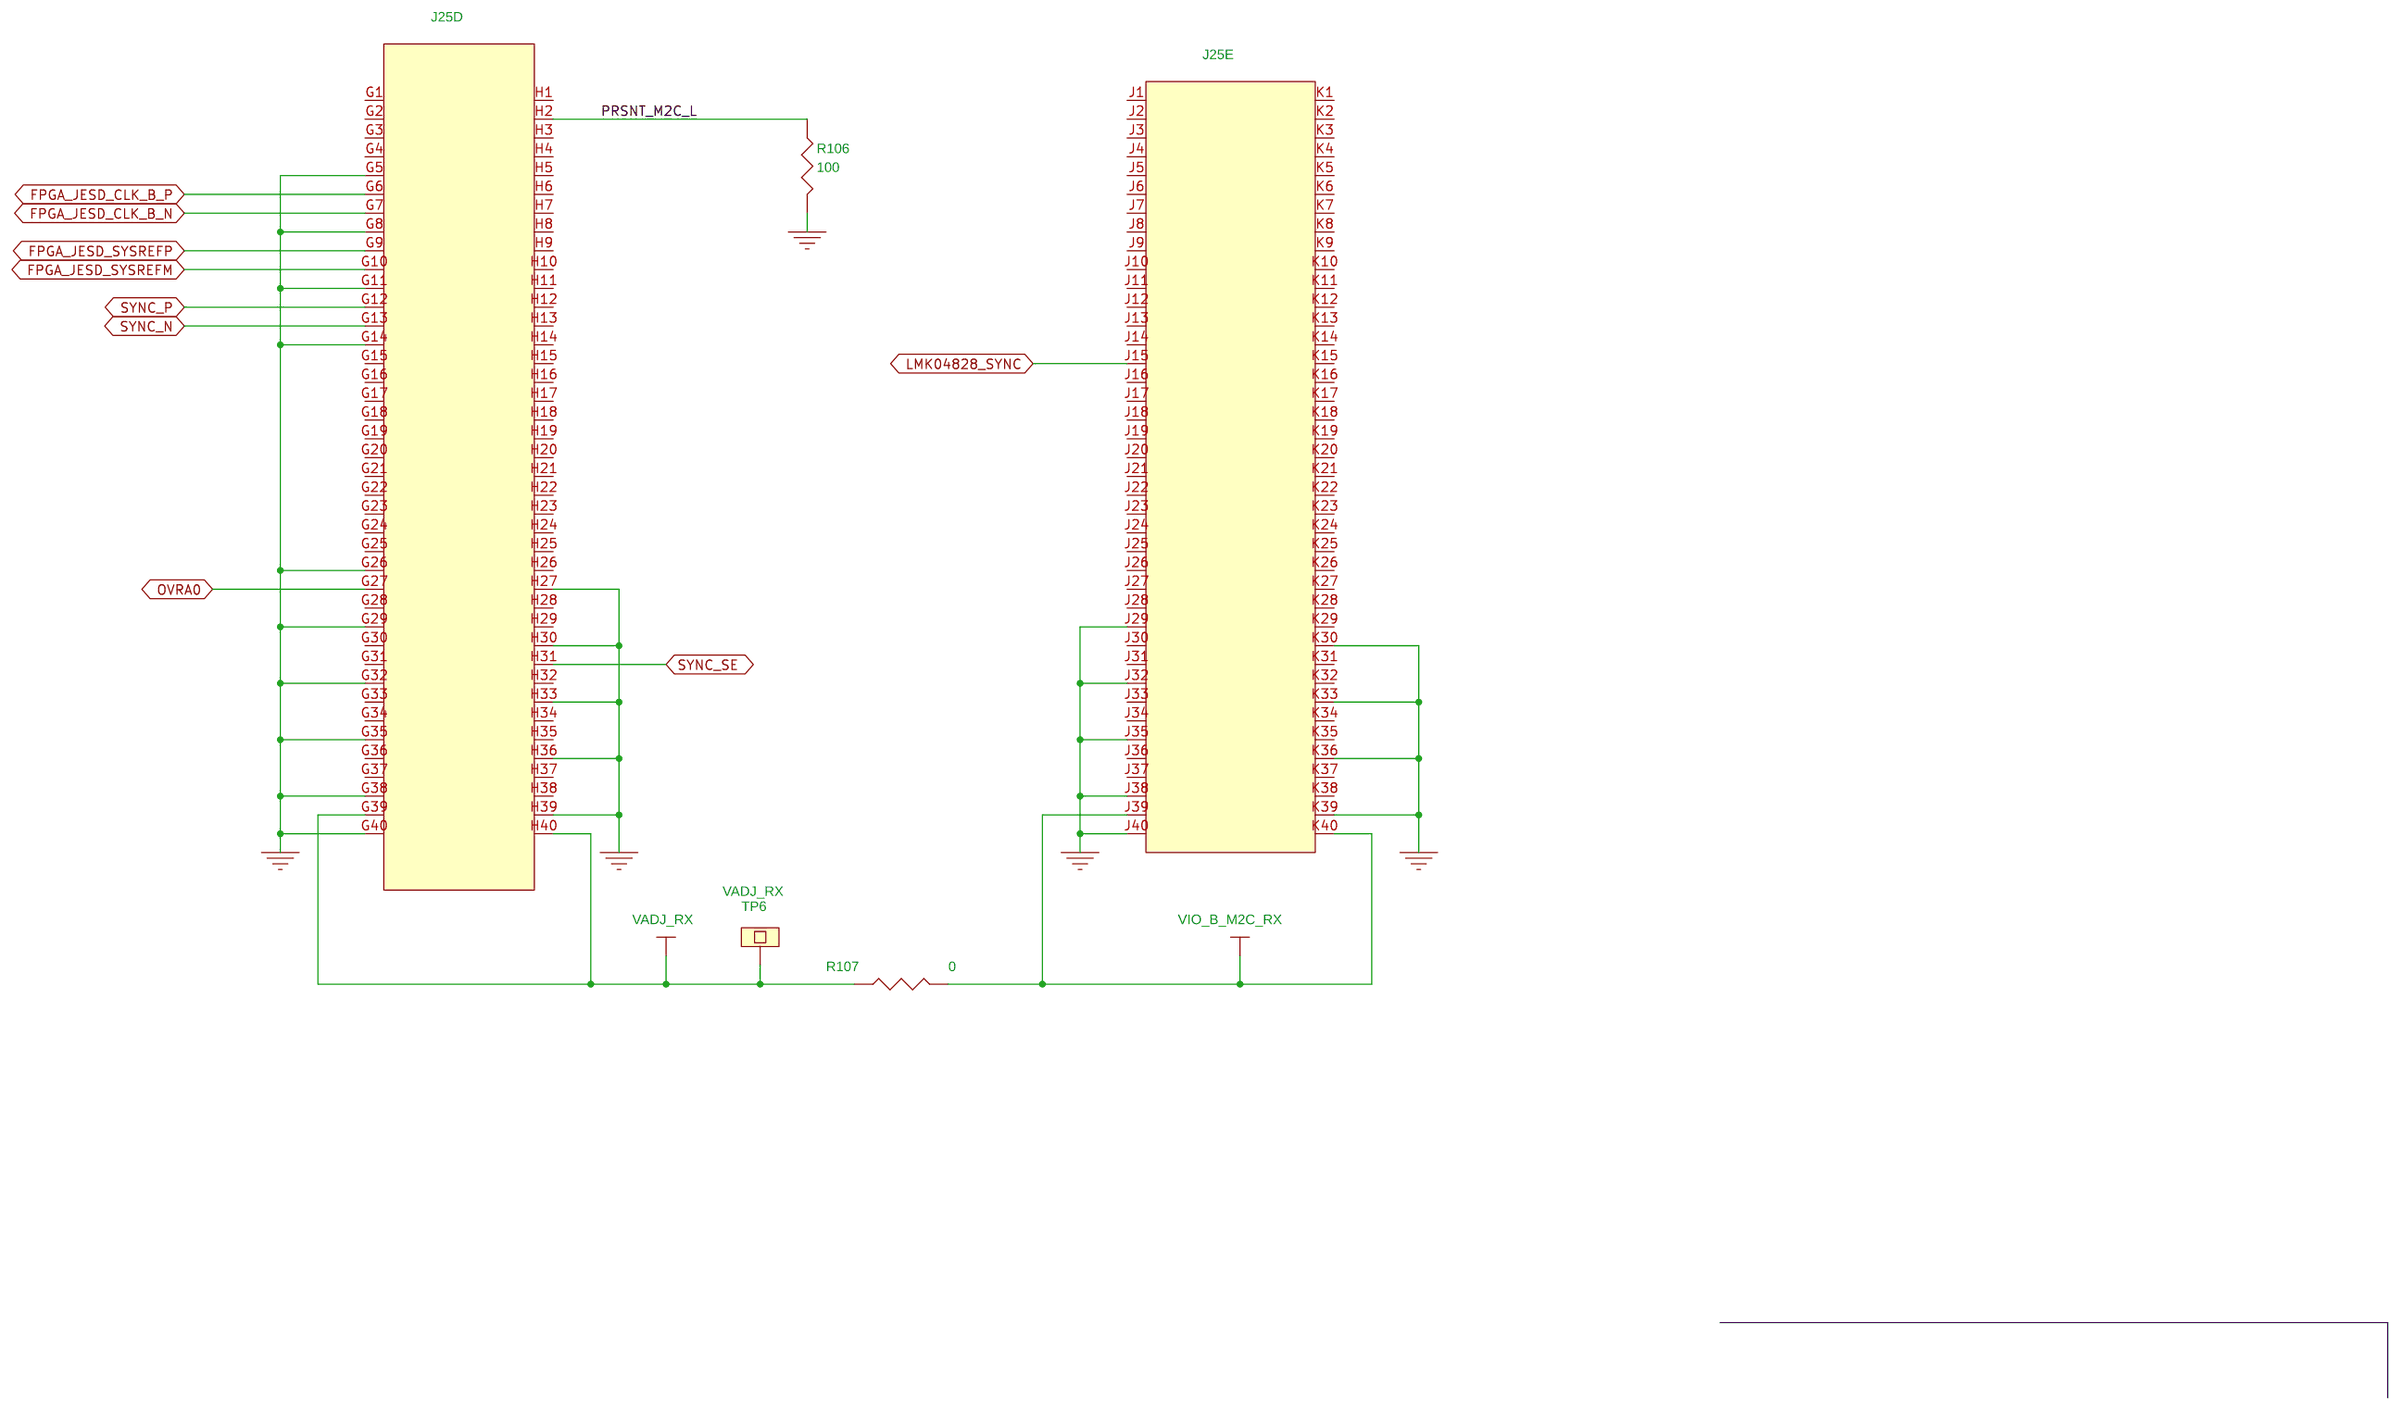
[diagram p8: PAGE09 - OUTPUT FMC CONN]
10 PAGE10 - OUTPUT FMC CONN: size B; title: OUTPUT - FMC CONNECTOR
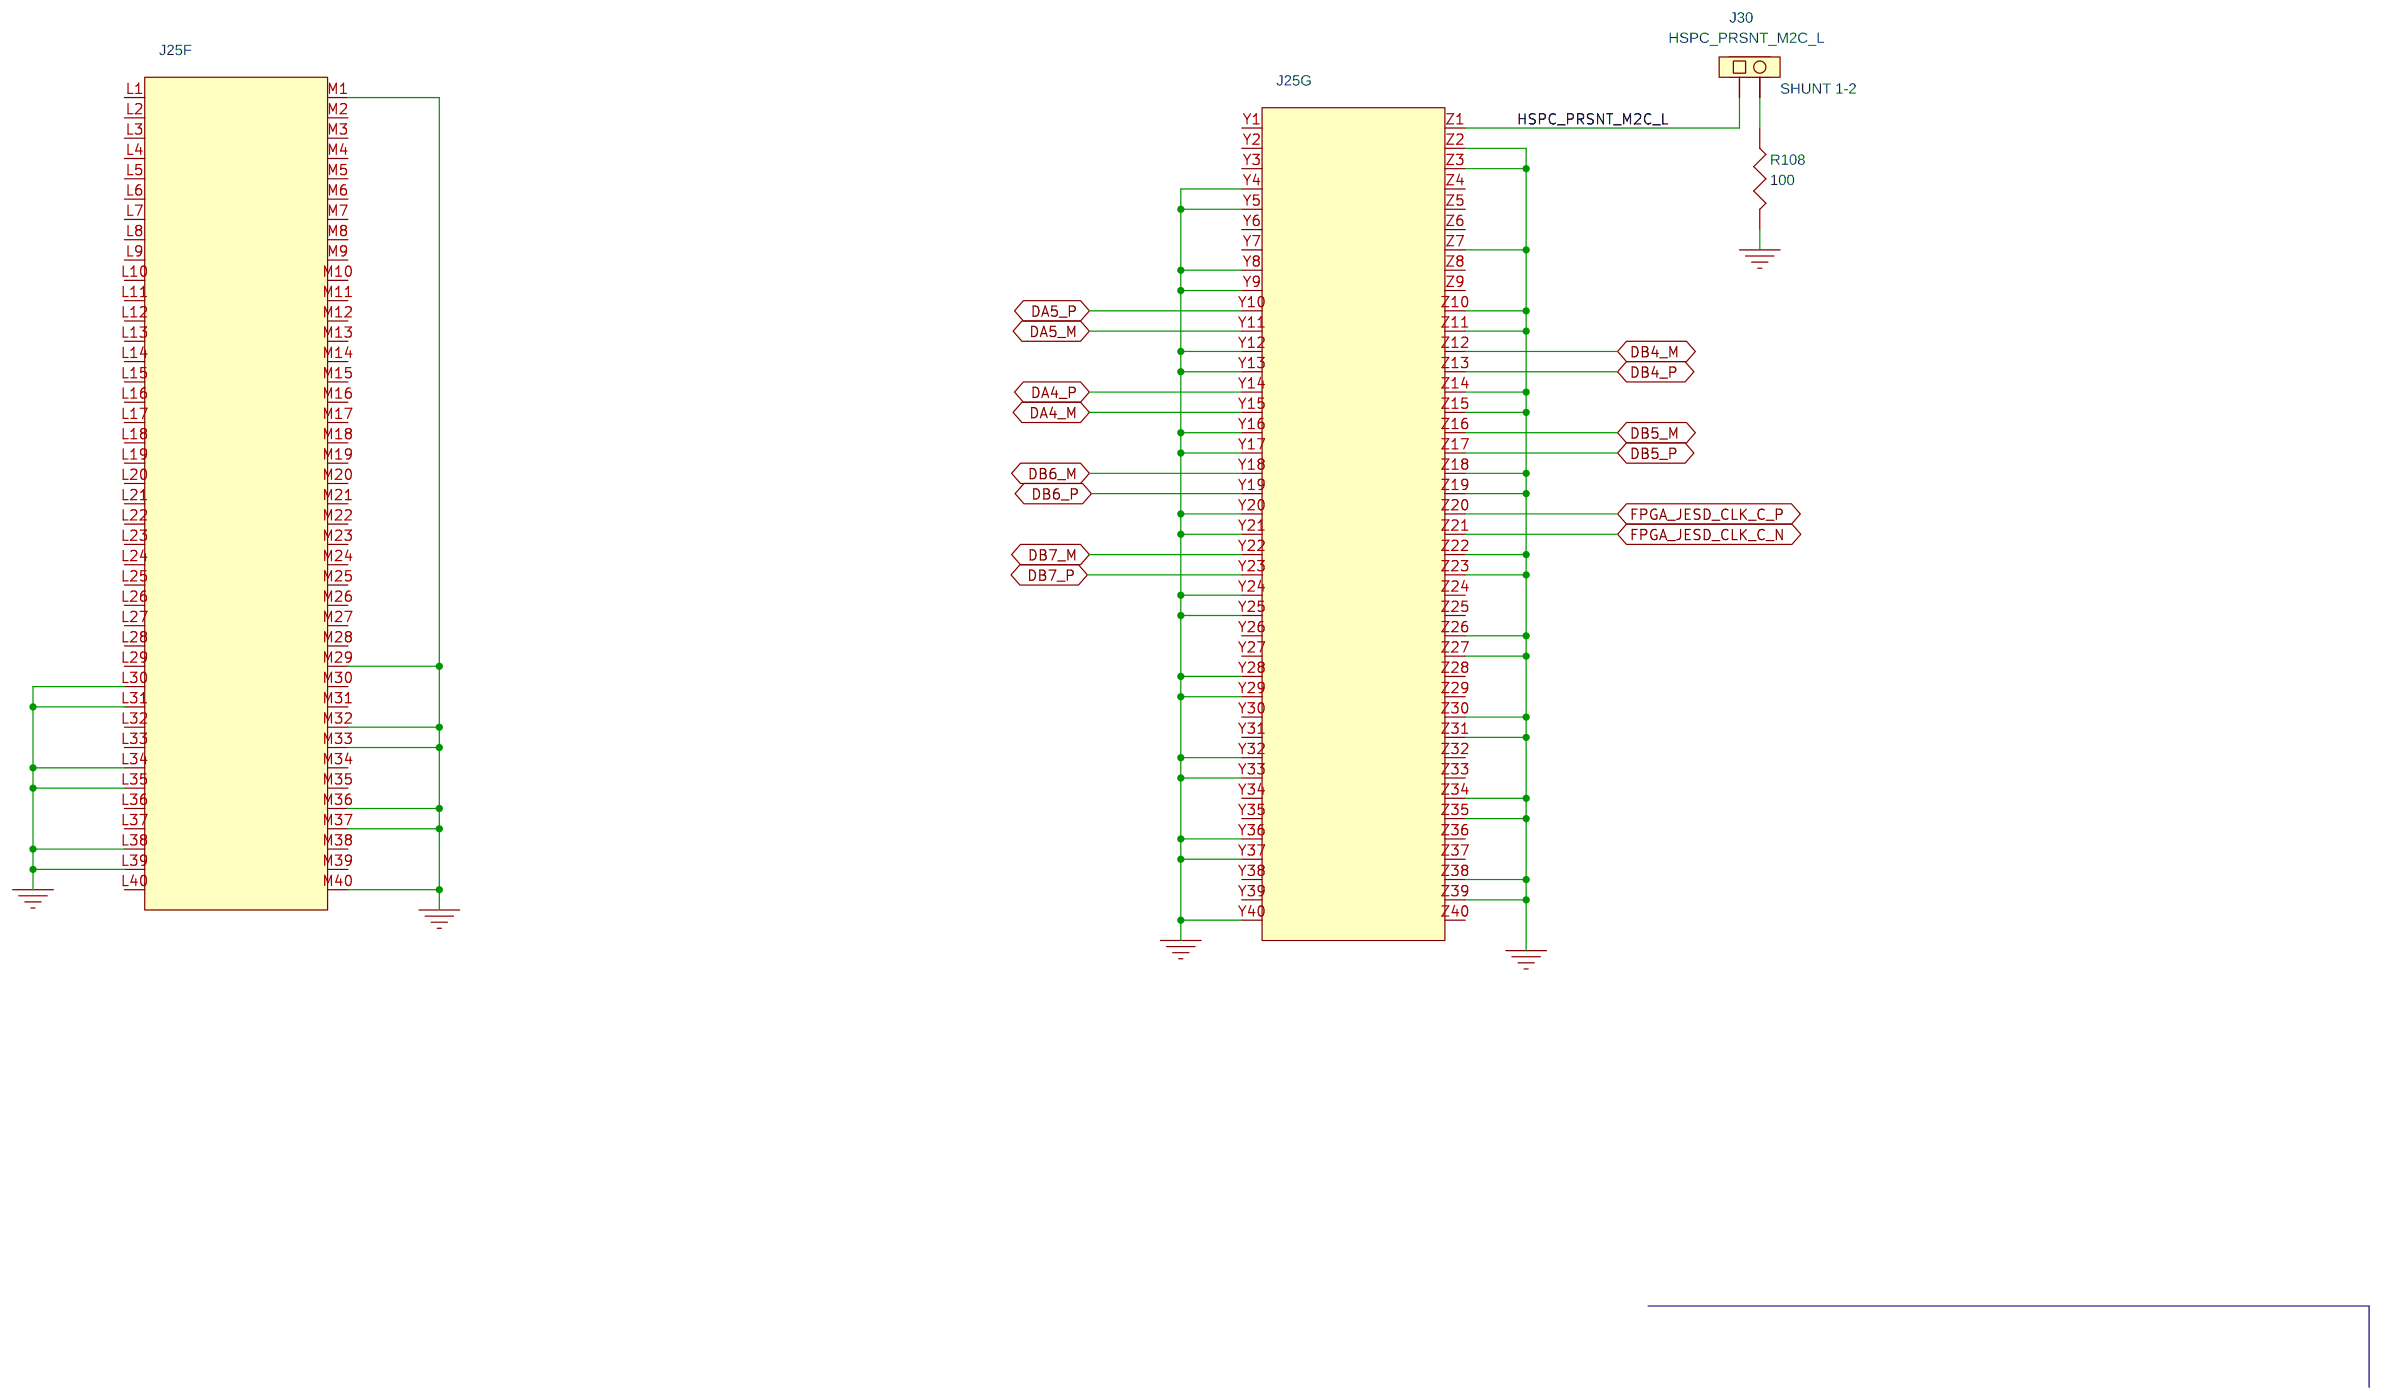
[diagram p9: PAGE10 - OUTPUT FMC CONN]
11 PAGE11 - USB: size B; title: USB
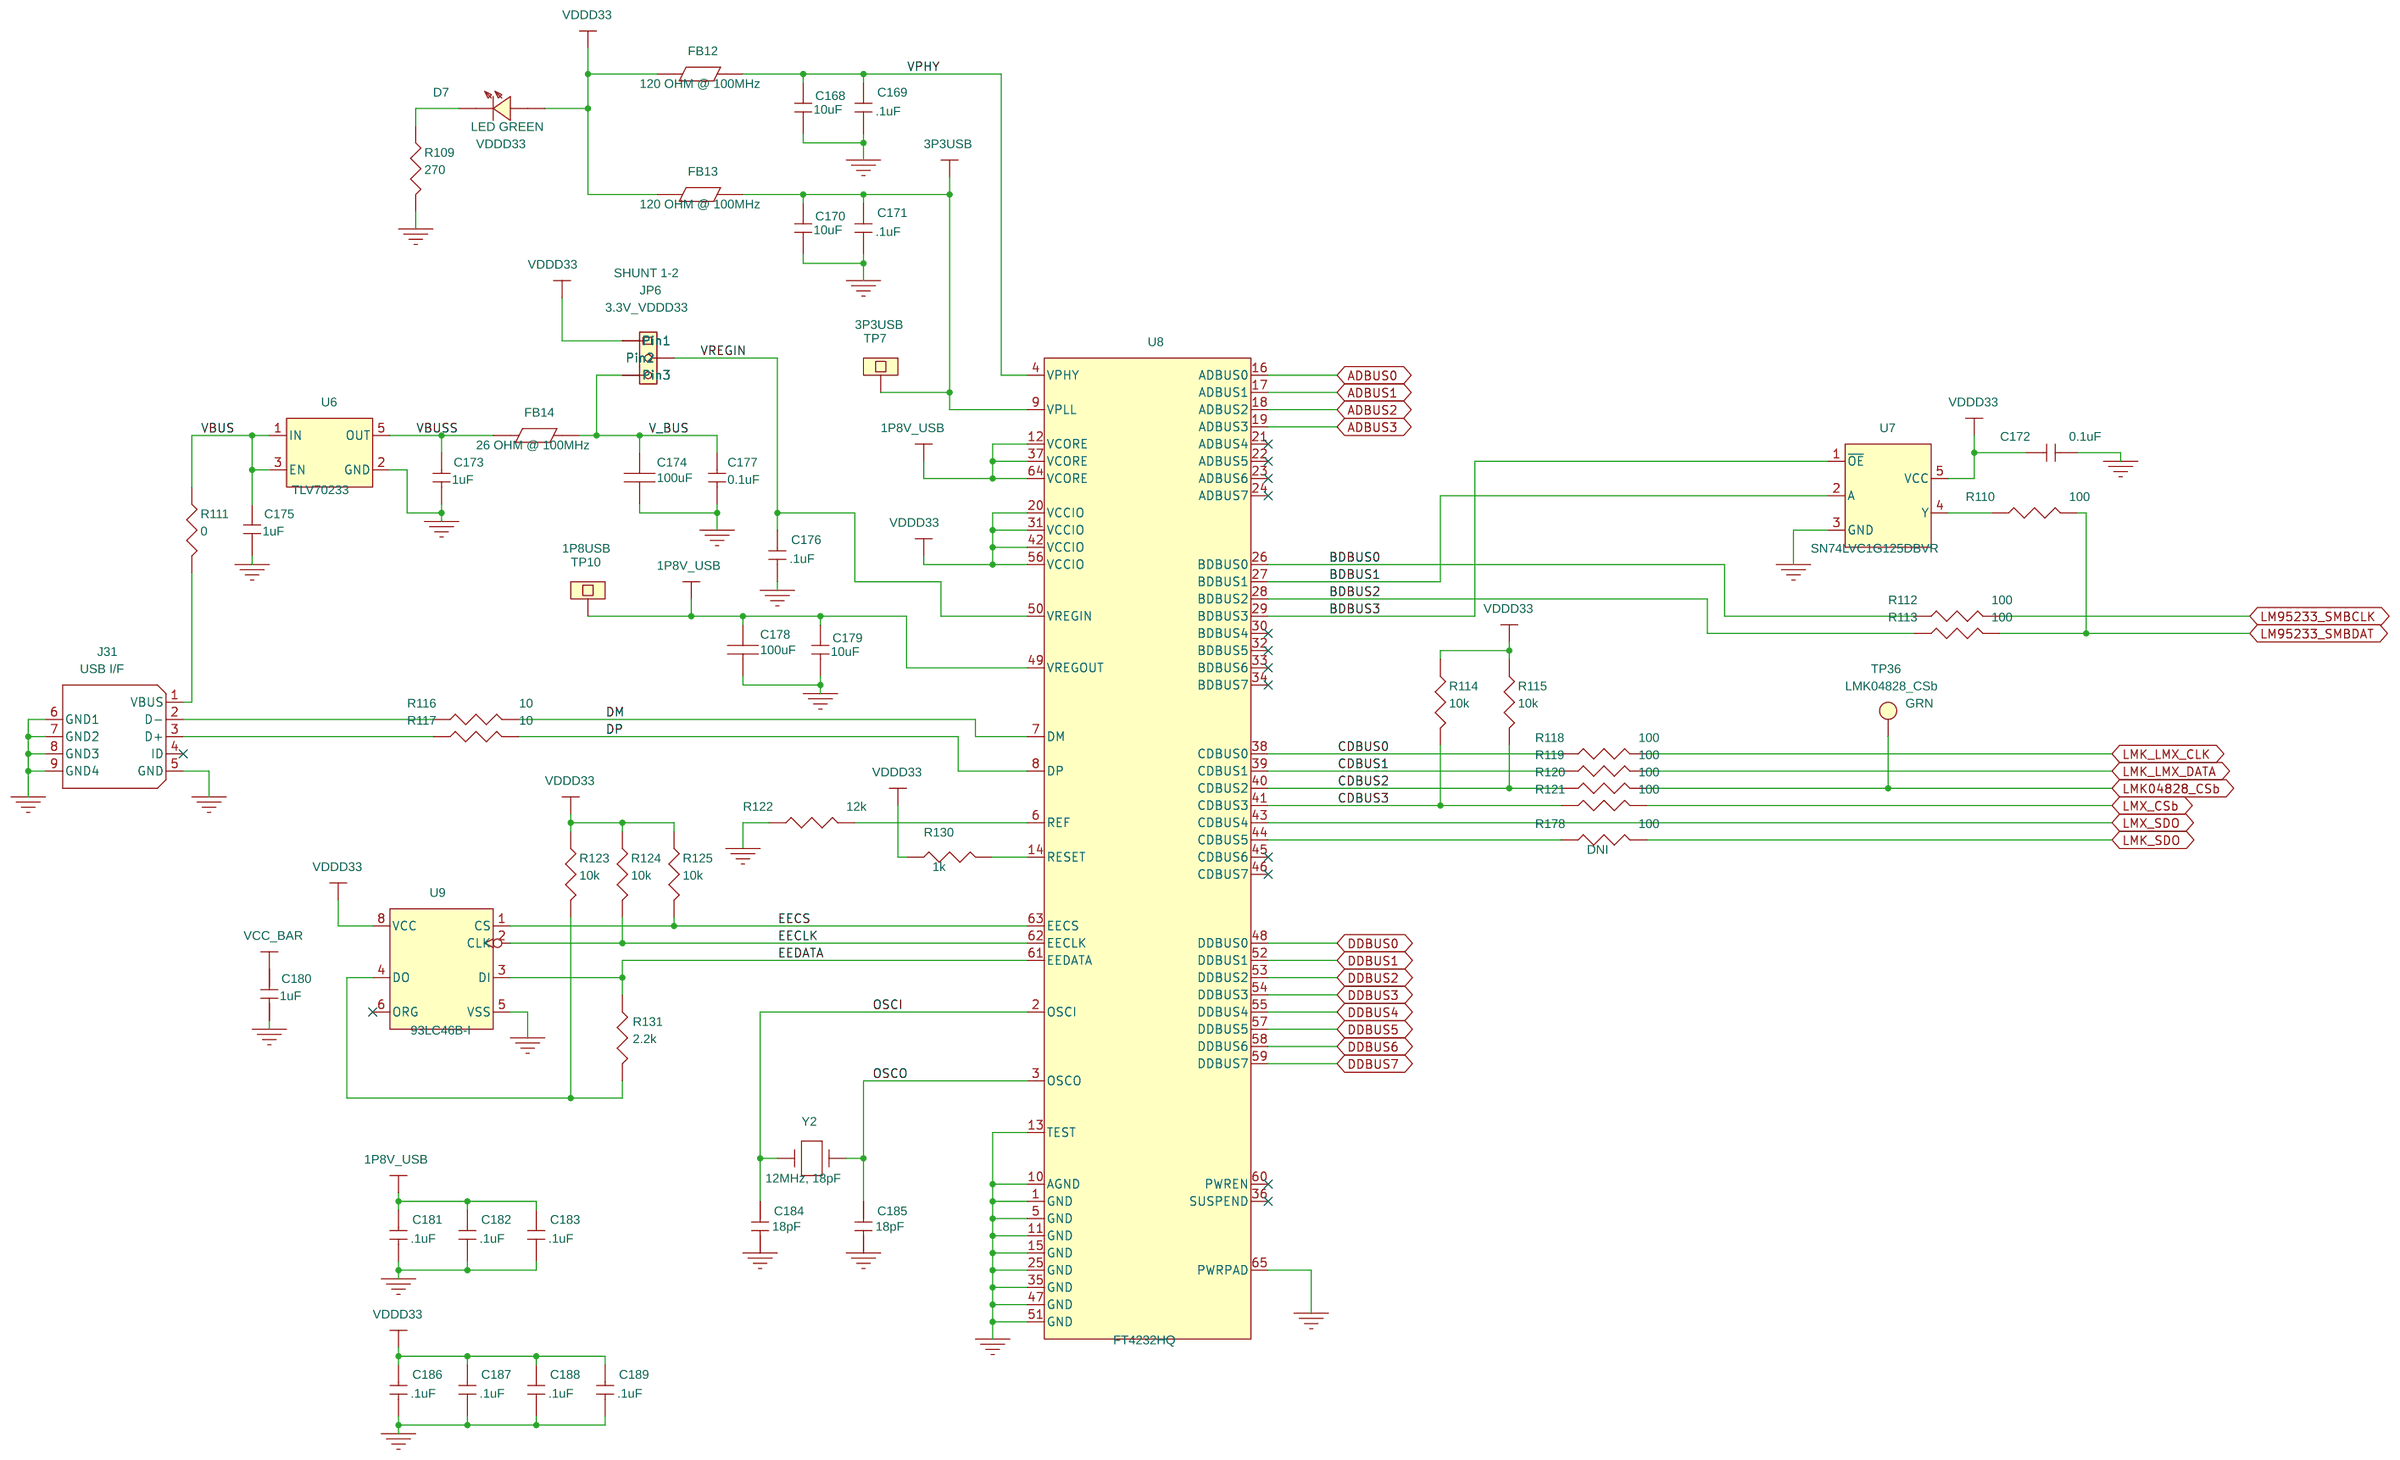
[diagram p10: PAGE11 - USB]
12 PAGE12 - LEVEL SHIFTERS: size B; title: LEVEL SHIFTERS
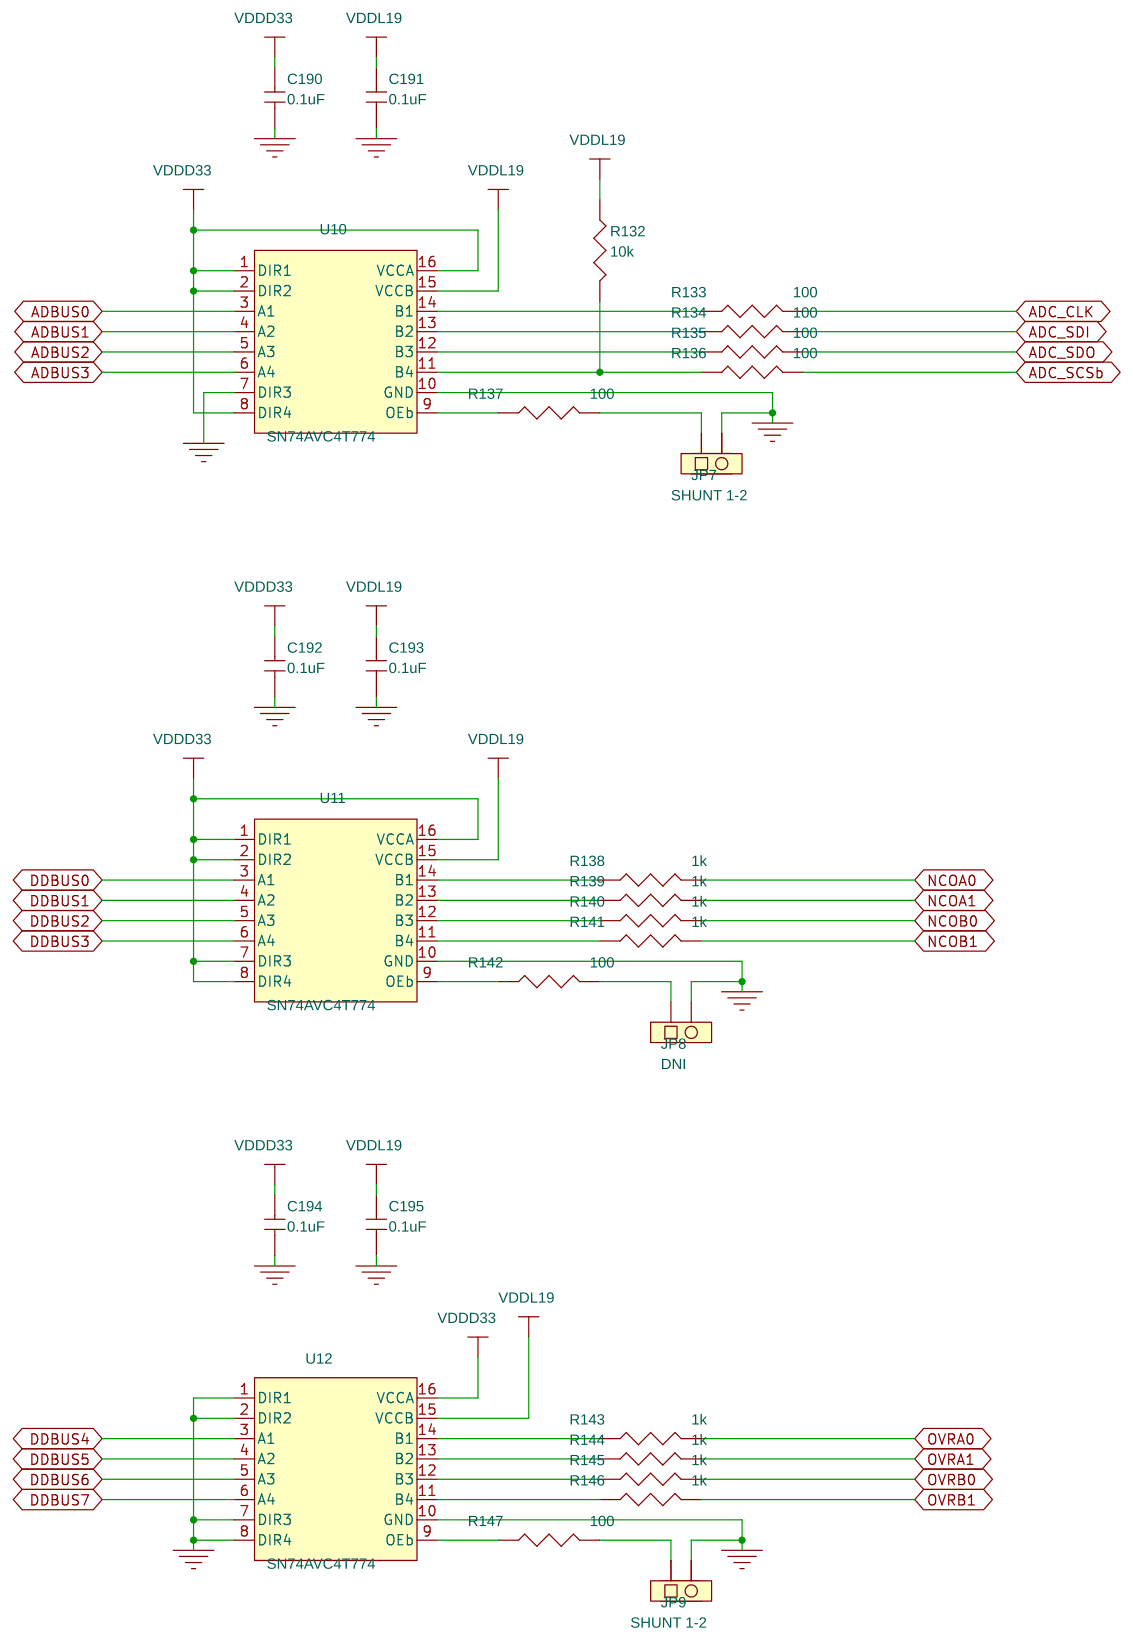
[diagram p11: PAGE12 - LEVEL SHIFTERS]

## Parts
sheet PAGE02 - ADC ANALOG INPUT
BALUN1  BALUN, HIGH POWER, SMT  [BALUN_320x320_MARKI_0006SMG]
BALUN2  BALUN, HIGH POWER, SMT  [BALUN_320x320_MARKI_0006SMG]
C5  .1uF  [0201]
C6  .1uF  [0201]
C7  .1uF  [0201]
C8  .1uF  [0201]
C9  .1uF  [0201]
C10  .1uF  [0201]
C11  .1uF  [0201]
C12  .1uF  [0201]
C13  .1uF  [0201]
C15  .1uF  [0201]
C16  .1uF  [0201]
C18  .1uF  [0201]
C19  .1uF  [0201]
C21  .1uF  [0201]
C22  .1uF  [0201]
C23  .1uF  [0201]
C25  .1uF  [0201]
C26  .1uF  [0201]
C27  .1uF  [0201]
C28  .1uF  [0201]
C29  .1uF  [0201]
C30  .1uF  [0201]
C31  .1uF  [0201]
C32  .1uF  [0201]
C33  .1uF  [0201]
C34  .1uF  [0201]
C35  .1uF  [0201]
C36  .1uF  [0201]
C37  .1uF  [0201]
C38  .1uF  [0201]
C39  .1uF  [0201]
C40  .1uF  [0201]
J1  SMA, THVT, SMT CENTER PIN  [SMA_THVT_SMT_250x250]
J2  SMA, JACK, 50 OHM, EDGE MNT  [SMA_SMEL_373x312]
J3  SMA, THVT, SMT CENTER PIN  [SMA_THVT_SMT_250x250]
J4  SMA, THVT, SMT CENTER PIN  [SMA_THVT_SMT_250x250]
J5  SMA, JACK, 50 OHM, EDGE MNT  [SMA_SMEL_373x312]
J6  SMA, THVT, SMT CENTER PIN  [SMA_THVT_SMT_250x250]
J7  HDR, THVT, 8POS, .100, GOLD  [HDR_THVT_2x4_100_M]
R1  0  [0201]
R4  0  [0201]
R6  0  [0201]
R9  0  [0201]
R11  10k  [0402]
R12  10k  [0402]
R13  1k  [0402]
R14  1k  [0402]
R15  1k  [0402]
R16  1k  [0402]
R17  10k  [0402]
R18  10k  [0402]
R151  0  [0201]
R162  0  [0201]
R179  0  [0201]
R180  0  [0201]
U1  ADC12DJXX00  [BGA_144_10MMx10MM_0p80MM]  (sections A,B,C)
sheet PAGE03 - ADC SPI
C1  0.1uF  [0603]
C2  1uF  [0603]
C3  .1uF  [0402]
C4  .1uF  [0402]
C14  .1uF  [0402]
C41  100pF  [0402]
C42  .1uF  [0402]
C43  10uF  [TANT_B]
C44  100pF  [0402]
C45  .1uF  [0402]
C46  100pF  [0402]
C47  .1uF  [0402]
C48  4700pF  [0402]
C49  4700pF  [0402]
C50  4700pF  [0402]
C51  4700pF  [0402]
C52  4700pF  [0402]
C53  4700pF  [0402]
D1  LED RED  [LED_0805]
D9  1N4148W  [DIODE_SM_1N4148W]
D10  LED ORANGE  [LED_0603]
D11  LED ORANGE  [LED_0603]
D12  1N4148W  [DIODE_SM_1N4148W]
J8  HDR, THVT, 2POS, .100, GOLD  [HDR_THVT_1x2_100_M]
J9  HDR, THVT, 2POS, .100, GOLD  [HDR_THVT_1x2_100_M]
J14  SMA, JACK, 50 OHM, EDGE MNT  [SMA_SMEL_373x312]
J15  SMA, JACK, 50 OHM, EDGE MNT  [SMA_SMEL_373x312]
J17  HDR, THVT, 2POS, .100, GOLD  [HDR_THVT_1x2_100_M]
J18  SMA, JACK, 50 OHM, EDGE MNT  [SMA_SMEL_373x312]
Q1  NPN, MMBT3904  [SOT_23_MMBT3904]
R19  1k  [0402]
R20  1k  [0402]
R21  10k  [0402]
R23  10k  [0402]
R25  1k  [0402]
R26  2.1k  [0402]
R27  10k  [0402]
R28  10k  [0402]
R29  10k  [0402]
R30  8.06k  [0402]
R31  1M  [0402]
R32  1.2k  [0402]
R33  1.33k  [0402]
R34  0  [0402]
R35  0  [0402]
R36  0  [0402]
R37  750  [0402]
R38  0  [0402]
R39  1.3k  [0402]
R40  0  [0402]
R41  1.3k  [0402]
R42  0  [0402]
R43  100  [0402]
R184  1M  [0402]
R185  1.2k  [0402]
T2  TC1-1-43X+  [TFMR_5_150x150_50]
TP1  ORN  [TP_THVT_100_RND]
TP2  ORN  [TP_THVT_100_RND]
TP3  ORN  [TP_THVT_100_RND]
TP25  ORN  [TP_THVT_100_RND]
TP26  ORN  [TP_THVT_100_RND]
U2  LM95233  [WSON_14_4MMx4MM_0p5]
U15  LMC6762  [SOIC_8_197x157_50]  (sections A,B)
sheet PAGE04 - ADC PWR
C54  .1uF  [0201]
C55  .1uF  [0201]
C56  .1uF  [0201]
C57  .1uF  [0201]
C58  .1uF  [0201]
C59  .1uF  [0201]
C60  .1uF  [0201]
C61  .1uF  [0201]
C62  .1uF  [0201]
C63  .1uF  [0201]
C64  .1uF  [0201]
C65  .1uF  [0201]
C66  1uF  [0402]
C67  1uF  [0402]
C68  10uF  [TANT_B]
C69  .1uF  [0201]
C70  .1uF  [0201]
C71  .1uF  [0201]
C72  .1uF  [0201]
C73  .1uF  [0201]
C74  .1uF  [0201]
C75  .1uF  [0201]
C76  .1uF  [0201]
C77  .1uF  [0201]
C78  .1uF  [0201]
C79  .1uF  [0201]
C80  .1uF  [0201]
C81  1uF  [0402]
C82  1uF  [0402]
C83  10uF  [TANT_B]
C84  .1uF  [0201]
C85  .1uF  [0201]
C86  .1uF  [0201]
C87  .1uF  [0201]
C88  .1uF  [0201]
C89  .1uF  [0201]
C90  .1uF  [0201]
C91  .1uF  [0201]
C92  .1uF  [0201]
C93  1uF  [0402]
C94  1uF  [0402]
C95  10uF  [TANT_B]
C96  .1uF  [0201]
TP31  PROBE POINT  [PROBE_POINT_30PAD]
TP32  PROBE POINT  [PROBE_POINT_30PAD]
TP33  PROBE POINT  [PROBE_POINT_30PAD]
sheet PAGE05 - LMX
C99  100pF  [0201]
C100  .1uF  [0201]
C101  .1uF  [0201]
C102  1uF  [0402]
C103  .1uF  [0201]
C104  .1uF  [0201]
C105  100pF  [0201]
C106  .1uF  [0201]
C107  .1uF  [0201]
C108  100pF  [0201]
C109  .1uF  [0201]
C110  100pF  [0201]
C111  1uF  [0402]
C112  10uF  [0603]
C113  .1uF  [0201]
C114  1uF  [0402]
C115  10uF  [0603]
C116  10uF  [0603]
C117  1uF  [0402]
C118  10uF  [0603]
C119  560pF  [0201]
C120  .047uF  [0201]
C121  6800pF  [0201]
C122  6800pF  [0201]
D2  LED GREEN  [LED_0805]
J20  SMP, PCB, SMT  [SMP_B120]
JP5  HDR, THVT, 2POS, .100, GOLD  [HDR_THVT_1x2_100_M]
R44  49.9  [0402]
R45  49.9  [0402]
R46  12k  [0402]
R47  100  [0402]
R48  49.9  [0402]
R49  49.9  [0402]
R50  680  [0201]
R51  680  [0201]
R52  49.9  [0201]
R53  49.9  [0201]
R54  0  [0201]
R55  12  [0201]
R56  150  [0201]
U3  LMX2582  [qfn40_RTA_RTB_RHA]
sheet PAGE06 - LMK
C20  .1uF  [0201]
C24  .1uF  [0201]
C128  .68uF  [0402]
C130  .1uF  [0201]
C131  3900pF  [0201]
C132  47pF  [0201]
C133  .1uF  [0201]
C134  .01uF  [0201]
C135  .1uF  [0201]
C136  .01uF  [0201]
C137  .1uF  [0201]
C138  .1uF  [0201]
C139  100pF  [0402]
C140  2200pF  [0402]
C141  10pF  [0402]
C142  .1uF  [0201]
C143  .1uF  [0201]
C144  .1uF  [0201]
C145  .1uF  [0201]
C146  .1uF  [0201]
C149  .1uF  [0201]
C150  .1uF  [0201]
C151  .1uF  [0201]
C152  12pF  [0201]
C153  .1uF  [0201]
C249  .1uF  [0201]
C250  .1uF  [0201]
FB1  120 OHM @ 100MHz  [IND_0603]
J22  SMA_THVT_REC  [SMA_THVT_312x312]
J23  SMA, THVT, SMT CENTER PIN  [SMA_THVT_SMT_250x250]
J24  SMA, THVT, SMT CENTER PIN  [SMA_THVT_SMT_250x250]
J38  SMA_THVT_REC  [SMA_THVT_312x312]
R22  0  [0201]
R24  0  [0201]
R57  240  [0201]
R58  240  [0201]
R59  0  [0201]
R60  0  [0201]
R61  240  [0201]
R62  240  [0201]
R63  39k  [0201]
R64  240  [0201]
R65  240  [0201]
R66  620  [0201]
R67  0  [0402]
R68  49.9  [0201]
R69  0  [0603]
R70  18  [0402]
R71  294  [0402]
R72  294  [0402]
R73  100  [0402]
R74  120  [0201]
R75  120  [0201]
R76  0  [0201]
R77  0  [0201]
R78  120  [0201]
R79  120  [0201]
R80  100  [0201]
R81  100  [0201]
R82  130  [0201]
R83  100  [0201]
R84  82  [0201]
R85  49.9  [0201]
R86  240  [0201]
R87  240  [0201]
R88  130  [0201]
R89  240  [0201]
R90  240  [0201]
R91  100  [0201]
R92  82  [0201]
R93  49.9  [0201]
R94  240  [0201]
R95  240  [0201]
R126  0  [0201]
R127  0  [0201]
R128  0  [0201]
R129  0  [0201]
R186  0  [0201]
R187  51  [0201]
R188  240  [0201]
R189  240  [0201]
SJP1  SOLDER JUMPER, 0402  [SMD_JUMPER_L_0402]
T1  TC1-1-13M+  [TFMR_5_150x150_50]
Y1  100.00MHz  [VCXO_6_CUSTOM]
sheet PAGE07 - LMK POWER
C154  1uF  [0402]
C155  .1uF  [0402]
C156  0.01uF  [0402]
C157  1uF  [0402]
C158  1uF  [0402]
C159  1uF  [0402]
C160  1uF  [0402]
C161  .1uF  [0402]
C162  0.01uF  [0402]
C163  .1uF  [0402]
C164  10uF  [0603]
C165  1uF  [0402]
C166  1uF  [0402]
D3  LED GREEN  [LED_0805]
D4  LED GREEN  [LED_0805]
D5  LED GREEN  [LED_0805]
D6  LED GREEN  [LED_0805]
FB2  120 OHM @ 100MHz  [IND_0603]
FB3  120 OHM @ 100MHz  [IND_0603]
FB4  120 OHM @ 100MHz  [IND_0603]
FB5  120 OHM @ 100MHz  [IND_0603]
FB6  120 OHM @ 100MHz  [IND_0603]
FB7  120 OHM @ 100MHz  [IND_0603]
FB8  120 OHM @ 100MHz  [IND_0603]
FB9  120 OHM @ 100MHz  [IND_0603]
FB10  120 OHM @ 100MHz  [IND_0603]
FB11  120 OHM @ 100MHz  [IND_0603]
R96  2.32k  [0402]
R97  0  [0402]
R98  0  [0402]
R99  10k  [0402]
R100  750  [0603]
R101  750  [0603]
R102  750  [0603]
R103  750  [0603]
TP4  ORN  [TP_THVT_100_RND]
U4  LMK04828  [QFN_64_360X360_0P50MM_PWRPAD]  (sections A,B)
sheet PAGE08 - OUTPUT FMC CONN
C167  1uF  [0402]
J25  CON, SMVT, HS, FIELD ARRAY, FMC, MALE  [CON_SMVT_40X14_50_M_MTG]  (sections A,B,C,D,E,F,G)
J26  HDR, THVT, 2POS, .100, GOLD  [HDR_THVT_1X2_100_M]
J27  HDR, THVT, 2POS, .100, GOLD  [HDR_THVT_1X2_100_M]
J28  HDR, THVT, 4POS, .100, GOLD  [HDR_THVT_1x4_100_M]
R104  4.99k  [0402]
R105  0  [0402]
TP5  PROBE POINT  [PROBE_POINT_30PAD]
U5  24LC65  [SO_8_207x207_50]
sheet PAGE09 - OUTPUT FMC CONN
R106  100  [0603]
R107  0  [0402]
TP6  PROBE POINT  [PROBE_POINT_30PAD]
sheet PAGE10 - OUTPUT FMC CONN
J30  HDR, THVT, 2POS, .100, GOLD  [HDR_THVT_1X2_100_M]
R108  100  [0201]
Z_SH-J5  SHUNT- HEADER
sheet PAGE11 - USB
C168  10uF  [0603]
C169  .1uF  [0201]
C170  10uF  [0603]
C171  .1uF  [0201]
C172  0.1uF  [0603]
C173  1uF  [0603]
C174  100uF  [1206]
C175  1uF  [0603]
C176  .1uF  [0201]
C177  0.1uF  [0603]
C178  100uF  [1206]
C179  10uF  [0603]
C180  1uF  [0603]
C181  .1uF  [0201]
C182  .1uF  [0201]
C183  .1uF  [0201]
C184  18pF  [0402]
C185  18pF  [0402]
C186  .1uF  [0201]
C187  .1uF  [0201]
C188  .1uF  [0201]
C189  .1uF  [0201]
D7  LED GREEN  [LED_0805]
FB12  120 OHM @ 100MHz  [IND_0603]
FB13  120 OHM @ 100MHz  [IND_0603]
FB14  26 OHM @ 100MHz  [IND_0603]
J31  CON, USB, MINI, AB, SMT  [CON_SMRT_USBMNE20_F]
JP6  HDR, THVT, 3POS, .100, GOLD  [HDR_THVT_1x3_100_M]
R109  270  [0402]
R110  100  [0402]
R111  0  [0603]
R112  100  [0402]
R113  100  [0402]
R114  10k  [0402]
R115  10k  [0402]
R116  10  [0603]
R117  10  [0603]
R118  100  [0402]
R119  100  [0402]
R120  100  [0402]
R121  100  [0402]
R122  12k  [0603]
R123  10k  [0402]
R124  10k  [0402]
R125  10k  [0402]
R130  1k  [0603]
R131  2.2k  [0603]
R178  100  [0402]
TP7  PROBE POINT  [PROBE_POINT_30PAD]
TP10  PROBE POINT  [PROBE_POINT_30PAD]
TP36  GRN  [TP_THVT_100_RND]
U6  TLV70233  [SOT_5_120x69_37]
U7  SN74LVC1G125DBVR  [SOT_5_120x69_57]
U8  FT4232HQ  [QFN_64_0p50MM_RGC_FT2232HQ]
U9  93LC46B-I  [MSOP_8_118x118_0p65MM]
Y2  12MHz, 18pF  [XTAL_2_SM_126x197]
Z_SH-H2  SHUNT- HEADER
sheet PAGE12 - LEVEL SHIFTERS
C190  0.1uF  [0603]
C191  0.1uF  [0603]
C192  0.1uF  [0603]
C193  0.1uF  [0603]
C194  0.1uF  [0603]
C195  0.1uF  [0603]
JP7  HDR, THVT, 2POS, .100, GOLD  [HDR_THVT_1X2_100_M]
JP8  HDR, THVT, 2POS, .100, GOLD  [HDR_THVT_1X2_100_M]
JP9  HDR, THVT, 2POS, .100, GOLD  [HDR_THVT_1X2_100_M]
R132  10k  [0402]
R133  100  [0402]
R134  100  [0402]
R135  100  [0402]
R136  100  [0402]
R137  100  [0402]
R138  1k  [0402]
R139  1k  [0402]
R140  1k  [0402]
R141  1k  [0402]
R142  100  [0402]
R143  1k  [0402]
R144  1k  [0402]
R145  1k  [0402]
R146  1k  [0402]
R147  100  [0402]
U10  SN74AVC4T774  [TSSOP_16_201x177_26]
U11  SN74AVC4T774  [TSSOP_16_201x177_26]
U12  SN74AVC4T774  [TSSOP_16_201x177_26]
Z_SH-J1  SHUNT- HEADER
Z_SH-J3  SHUNT- HEADER

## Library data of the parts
BALUN1 BALUN2 = BALUN_MARKI_SMG_320x320: Mfr_Part_Number: BAL-0006SMG
C5-C13 C15 C16 C18 C19 C21-C23 C25-C40 C138 C149 = CAP_0402_0.1uF_H: Mfr_Part_Number: GRM033R61A104KE15D; TOL: 10%; Voltage: 16V
J1 = SMA_THVT_SMA_CENTER_PIN: TI_Silktext: INA+
J2 = SMA_END_HIGH_FREQ_PSF-S01_0: Mfr_Name: Johnson Components; Mfr_Part_Number: 142-0701-801; TI_Silktext: VINA
J3 = SMA_THVT_SMA_CENTER_PIN: TI_Silktext: INA-
J4 = SMA_THVT_SMA_CENTER_PIN: TI_Silktext: INB+
J5 = SMA_END_HIGH_FREQ_PSF-S01_0: Mfr_Name: Johnson Components; Mfr_Part_Number: 142-0701-801; TI_Silktext: VINB
J6 = SMA_THVT_SMA_CENTER_PIN: TI_Silktext: INB-
J7 = HEADER_2x4_100: Mfr_Part_Number: HTSW-104-07-G-D; TI_SILKTEXT: NCO
R1 R4 R6 R9 = Res_0201_Zero_H: Mfr_Part_Number: ERJ-1GE0R00C
R11 R12 R17 R18 R21 R23 R27-R29 R114 R115 R123-R125 R132 = Res_0402_10k
R13-R16 = Res_0402_1k_H
R151 R162 R179 R180 = Res_0201_Zero_H: Mfr_Part_Number: ERJ-1GE0R00C_DNI; Note: DNI
U1 = ADC12DJXX00: Mfr_Part_Number: ADC12DJ3200AAV
C1 = CAP_0603_0.1uF: Mfr_Part_Number: 0603YC104JAT2A
C2 = CAP_0603_1uF: Mfr_Name: TDK; Mfr_Part_Number: C1608X5R1A105K080AC
C3 C4 C14 C45 C47 = CAP_0402_4700pF_H: Mfr_Name: MURATA; Mfr_Part_Number: GRM155R71C104KA88D
C41 C44 C46 = CAP_0603_100pF: Mfr_Part_Number: 04025A101JAT2A
C42 = CAP_0603_0.1uF: Mfr_Name: MURATA; Mfr_Part_Number: GRM155R71C104KA88D
C43 C68 C83 C95 = CAP_TANT_B_10uF_10V: Mfr_Name: Vishay Sprague; Mfr_Part_Number: 293D106X0010B2TE3
C48 C49 C52 C53 = CAP_0402_4700pF_H: Mfr_Part_Number: CC0402KRX7R8BB472_DNI; Note: DNI
C50 C51 = CAP_0402_4700pF_H
D1 = LED_RED_0: TI_SILKTEXT: TEMP
D9 D12 = DIODE_1N4148W
D10 = LED_ORANGE_0603: SILK: OVRB0
D11 = LED_ORANGE_0603: SILK: OVRA0
J8 = HEADER_1x2_100: Mfr_Part_Number: HTSW-102-07-G-S; TI_SILKTEXT: PD
J9 = HEADER_1x2_100: Mfr_Part_Number: HTSW-102-07-G-S; TI_SILKTEXT: CALTRG
J14 = SMA_END_HIGH_FREQ_PSF-S01_0: Mfr_Name: Johnson Components; Mfr_Part_Number: 142-0701-801; TI_Silktext: TMSTP+
J15 = SMA_END_HIGH_FREQ_PSF-S01_0: Mfr_Name: Johnson Components; Mfr_Part_Number: 142-0701-801; TI_Silktext: TMSTP-
J17 = HEADER_1x2_100: Mfr_Part_Number: HTSW-102-07-G-S_DNI; Note: DNI; TI_SILKTEXT: TDIODE
J18 = SMA_END_HIGH_FREQ_PSF-S01_0: Mfr_Name: Johnson Components; Mfr_Part_Number: 142-0701-801; TI_Silktext: DEVCLK+
Q1 = NPN_MMBT3904: Mfr_Name: Fairchild Semi; Mfr_Part_Number: MMBT3904
R19 R20 R25 = Res_0402_1k
R26 = Res_0402_2.1K
R30 = Res_0402_8.06k
R31 R184 = Res_0402_1M
R32 R185 = Res_0402_1.2k
R33 = Res_0402_1.33k
R34 R38 R97 = Res_0402_Zero_H
R35 R36 R98 = Res_0402_Zero_H: Mfr_Part_Number: ERJ-2GE0R00X_DNI; Note: DNI
R37 = Res_0603_750_H: Mfr_Part_Number: ERJ-2RKF7500X
R39 R41 = Res_0603_1.3k_H: Mfr_Part_Number: ERJ-2RKF1301X
R40 R42 = Res_0402_Zero_H: Mfr_Part_Number: ERJ-2GE0R00X
R43 R47 = Res_0402_100_H
T2 = TFMR_5_TC1-1-43X+: Mfr_Part_Number: TC1-1-43X-2+
TP1 = TESTPOINT_ORANGE: TI_SILKTEXT: TCRIT1
TP2 = TESTPOINT_ORANGE: TI_SILKTEXT: TCRIT2
TP3 = TESTPOINT_ORANGE: TI_SILKTEXT: TCRIT3
TP25 = TESTPOINT_ORANGE: TI_SILKTEXT: CALSTAT
TP26 = TESTPOINT_ORANGE: TI_SILKTEXT: BG
U2 = LM95233
U15 = LMC6762: Mfr_Part_Number: LMC6762AIM/NOPB
C54-C65 C69-C80 C84-C92 C96 = CAP0402_0: Mfr_Name: MURATA; Mfr_Part_Number: GRM033R61A104KE15D; TOL: 10%; Voltage: 16V
C66 C67 C81 C82 C93 C94 = CAP_NP_1: Mfr_Name: TDK; Mfr_Part_Number: C1005X7S1A105K050BC; TOL: 10%; VOLTAGE: 10V
TP31 = PROBE_POINT_0: TI_Silktext: VA11
TP32 = PROBE_POINT_0: TI_Silktext: VA19
TP33 = PROBE_POINT_0: TI_Silktext: VD11
C99 C105 C108 C110 = CAP_0603_100pF_H: Mfr_Name: MURATA; Mfr_Part_Number: GRM0335C1E101JA01D
C20 C24 C100 C101 C103 C104 C106 C107 C109 C113 C133 C135 C142 C143 C146 C249 C250 = CAPACITOR_NP_1: Mfr_Name: MURATA; Mfr_Part_Number: GRM033R61A104KE15D; TOL: 10%; Voltage: 16V
C102 C111 C114 C117 = CAP_NP_0: Mfr_Name: TDK; Mfr_Part_Number: C1005X7S1A105K050BC; TOL: 10%; VOLTAGE: 10V
C112 C115 C116 C118 = CAP_NP_1: Mfr_Name: TDK; Mfr_Part_Number: C1608X5R1A106K080AC; TOL: 10%; VOLTAGE: 10V
C119 = CAP_NP_0: Mfr_Name: MURATA; Mfr_Part_Number: GRM033R71E561KA01D; TOL: 10%; VOLTAGE: 25V
C120 = CAP_NP_0: Mfr_Name: MURATA; Mfr_Part_Number: GRM033R61C473KE84D; TOL: 10%; VOLTAGE: 16V
C121 = CAP_NP_0: Mfr_Name: MURATA; Mfr_Part_Number: GRM033R71A682KA01D_DNI; Note: DNI; TOL: 10%; VOLTAGE: 10V
C122 = CAP_NP_0: Mfr_Name: MURATA; Mfr_Part_Number: GRM033R71A682KA01D; TOL: 10%; VOLTAGE: 10V
D2 = LED: Mfr_Name: LITE ON; Mfr_Part_Number: LTST-C170KGKT; TI_Silktext: MUXout
J20 = SMP_PLUG_SMT_0: Mfr_Name: MOLEX INC.; Mfr_Part_Number: 0853050232; TI_Silktext: RFOUTBP
JP5 = HDR_2x1_100: Mfr_Part_Number: HTSW-102-07-G-S; Note: OPEN
R44 R45 R48 R49 = Res_0402_49.9: Mfr_Part_Number: ERJ-2RKF49R9X
R46 = Res_0402_18: Mfr_Part_Number: ERJ-2RKF1202X
R50 = Res_0402_49.9: Mfr_Part_Number: ERJ-1GEF6800C_DNI; Note: DNI
R51 = Res_0402_49.9: Mfr_Part_Number: ERJ-1GEF6800C
R52 R53 R68 = Res_0402_49.9: Mfr_Part_Number: ERJ-1GEF49R9C_DNI; Note: DNI
R22 R24 R54 R59 R60 R76 R77 R126-R129 R186 = Res_0402_Zero_H_DNI: Mfr_Part_Number: ERJ-1GE0R00C
R55 = Res_0402_18: Mfr_Part_Number: ERJ-1GEF12R0C
R56 = R_1: Mfr_Name: PANASONIC; Mfr_Part_Number: ERJ-1GEJ151C
U3 = LMX2582_LM2592: Mfr_Name: Texas Instruments; Mfr_Part_Number: LMX2582RHAT
C128 = CAP_NP_0: Mfr_Name: TDK; Mfr_Part_Number: C1005X7S0J684K050BC; TOL: 10%; VOLTAGE: 6.3V
C130 C150 = CAP_NP_0: Mfr_Name: MURATA; Mfr_Part_Number: GRM033R61A104KE15D; TOL: 10%; VOLTAGE: 16V
C131 = CAP_NP_0: Mfr_Name: AVX; Mfr_Part_Number: 0201ZD392KAT2A; TOL: 10%; VOLTAGE: 10V
C132 = CAP_NP_0: Mfr_Name: MURATA; Mfr_Part_Number: GRM0335C1E470JA01D; TOL: 5%; VOLTAGE: 25V
C134 C136 = CAP_0402_0.01uF_H: Mfr_Part_Number: GRM033R71A103KA01D; TOL: 10%; VOLTAGE: 10V
C137 = CAP_0402_0.1uF: Mfr_Name: MURATA; Mfr_Part_Number: GRM033R61A104KE15D_DNI; Note: DNI; TOL: 10%; VOLTAGE: 16V
C139 = CAP_0603_100pF_H: Mfr_Name: TDK; Mfr_Part_Number: C1005C0G1H101J050BA
C140 = CAP_0402_2200pF_H: Mfr_Name: MURATA; Mfr_Part_Number: GRM155R71E222KA01D
C141 = CAP_0402_10pF_H: Mfr_Part_Number: GRM1555C1H100JA01D
C144 = CAP_0402_0.1uF_H: Mfr_Part_Number: GRM033R61A104KE15D_DNI; Note: DNI; TOL: 10%
C145 = CAP_NP_0: Mfr_Name: MURATA; Mfr_Part_Number: GRM033R61A104KE15D_DNI; Note: DNI; TOL: 10%; VOLTAGE: 16V
C151 C153 = CAPACITOR_NP_1: Mfr_Name: MURATA; Mfr_Part_Number: GRM033R61A104KE15D_DNI; Note: DNI; TOL: 10%; Voltage: 16V
C152 = CAPACITOR_NP_1: Mfr_Name: TDK; Mfr_Part_Number: CGA1A2C0G1E120J030BA; TOL: 2%; Voltage: 25V
FB1 = FERRITE_BEAD_0402_H: Isat: 500mA; Mfr_Name: MURATA; Mfr_Part_Number: BLM18SG121TN1D
J22 = SMA-THVT_142-0701-201_REC_0: TI_Silktext: LMK_CLKIN
J23 = SMA_THVT_SMA_CENTER_PIN: TI_Silktext: DCLKOUT10P
J24 = SMA_THVT_SMA_CENTER_PIN: TI_Silktext: DCLKOUT10N
J38 = SMA-THVT_142-0701-201_REC_0: TI_Silktext: CLKIN0
R57 R58 R61 R62 R64 R65 R89 R90 = Res_0402_249: Mfr_Part_Number: ERJ-1GEF2400C_DNI; Note: DNI
R63 = R_1: Mfr_Name: PANASONIC; Mfr_Part_Number: ERJ-1GEF3902C
R66 = R_1: Mfr_Name: PANASONIC; Mfr_Part_Number: ERJ-1GEF6200C
R67 = R: Mfr_Name: PANASONIC; Mfr_Part_Number: ERJ-2GE0R00X
R69 = Res_0603_Zero_DNI: Mfr_Part_Number: ERJ-3GEY0R00V_DNI; Note: DNI
R70 = Res_0402_18: Mfr_Part_Number: ERJ-2RKF18R0X_DNI; Note: DNI
R71 = Res_0402_270: Mfr_Part_Number: ERJ-2RKF2940X
R72 = Res_0402_270: Mfr_Part_Number: ERJ-2RKF2940X_DNI; Note: DNI
R73 = Res_0603_100: Mfr_Part_Number: ERJ-2RKF1000X
R74 R75 R78 R79 = Res_0402_249: Mfr_Part_Number: ERJ-1GEF1200C
R80 R81 = Res_0603_100: Mfr_Part_Number: ERJ-1GEF1000C_DNI; Note: DNI
R82 = RESISTOR_0: Mfr_Name: PANASONIC; Mfr_Part_Number: ERJ-1GEF1300C_DNI; Note: DNI
R83 = Res_0402_100_H: Mfr_Part_Number: ERJ-1GEF1000C_DNI; Note: DNI
R84 R92 = RESISTOR_0: Mfr_Name: PANASONIC; Mfr_Part_Number: ERJ-1GEF82R0C_DNI; Note: DNI; TOL: 1%
R85 = RESISTOR_0: Mfr_Name: PANASONIC; Mfr_Part_Number: ERJ-1GEF49R9C_DNI; Note: DNI; TOL: 1%
R86 R87 R94 R95 R188 R189 = Res_0402_249: Mfr_Part_Number: ERJ-1GEF2400C
R88 = RESISTOR_0: Mfr_Name: PANASONIC; Mfr_Part_Number: ERJ-1GEF1300C_DNI; Note: DNI; TOL: 1%
R91 = Res_0402_100_H: Mfr_Part_Number: ERJ-1GEF1000C
R93 = RESISTOR_0: Mfr_Name: PANASONIC; Mfr_Part_Number: ERJ-1GEF49R9C; TOL: 1%
R187 = Res_0201_51_1%
SJP1 = SMD_JUMPER_1x3: Mfr_Name: DNI; Mfr_Part_Number: DNI; Note: DNI; TI_SILK: SHUNT 1-2; TI_Silktext: EN
T1 = TFMR_5_TC1-1-13M+: Mfr_Part_Number: TC1-1-13M-23+
Y1 = OSC_SM_6_TCO-2100-SERIES_2: Mfr_Name: Crystek; Mfr_Part_Number: CVHD-950-100.000
C154 C157-C160 C165 C166 = CAPACITOR_NP_1: Mfr_Name: TDK; Mfr_Part_Number: C1005X7S1A105K050BC; TOL: 10%; Voltage: 10V
C155 C161 C163 = CAPACITOR_NP_1: Mfr_Name: MURATA; Mfr_Part_Number: GRM155R71C104KA88D; TOL: 10%; Voltage: 16V
C156 C162 = CAPACITOR_NP_1: Mfr_Name: MURATA; Mfr_Part_Number: GRM155R71H103KA88D; TOL: 10%; Voltage: 50V
C164 = CAP_NP_2: CLASS: DISCRETE; Mfr_Name: MURATA; Mfr_Part_Number: GRM188R60J106ME47D; TOL: 10%; VOLTAGE: 16V
D3 = LED: Mfr_Name: LITE ON; Mfr_Part_Number: LTST-C170KGKT; TI_Silktext: STAT 0
D4 = LED: Mfr_Name: LITE ON; Mfr_Part_Number: LTST-C170KGKT; TI_Silktext: STAT 1
D5 = LED: Mfr_Name: LITE ON; Mfr_Part_Number: LTST-C170KGKT; TI_Silktext: LMK LOCKED
D6 = LED: Mfr_Name: LITE ON; Mfr_Part_Number: LTST-C170KGKT; TI_Silktext: PLL2 LOCKED
FB2-FB11 = FERRITE_BEAD_0402_H: Isat: 500mA; Mfr_Name: MURATA; Mfr_Part_Number: BLM18AG121SN1D
R96 = Res_0402_2.32K_H
R99 = Res_0402_1.3K: Mfr_Part_Number: ERJ-2RKF1002X
R100-R103 = RESISTOR_0: CLASS: DISCRETE; Mfr_Name: DALE; Mfr_Part_Number: CRCW0603750RFKEA
TP4 = TESTPOINT_BLUE: Mfr_Part_Number: 5003; TI_SILKTEXT: LMK_SYNC
U4 = LMK04828: Mfr_Name: Texas Instruments; Mfr_Part_Number: LMK04828BISQE/NOPB
C167 = CAP_NP_1: Mfr_Name: Samsung; Mfr_Part_Number: CL05B105KQ5NQNC
J25 = CON_SMVT_40X14_50_M
J26 = JUMPER_1X2_100: SILK: PG_RX1
J27 = JUMPER_1X2_100: SILK: JTAG Loopback
J28 = HEADER_1x4_100: TI_SILKTEXT: 3.3VAUX
R104 = Res_0402_4.99K
R105 R107 = Res_0402_Zero: Mfr_Part_Number: ERJ-2GE0R00X
TP5 = PROBE_POINT_0: TI_Silktext: 3.3VRX
U5 = 24LC65: Mfr_Name: MICROCHIP TECHNOLOGY_DNI; Mfr_Part_Number: 24C65T-I/SM_DNI; Note: DNI
R106 = Res_0201_100: Mfr_Part_Number: ERJ-3EKF1000V
TP6 = PROBE_POINT_0: TI_Silktext: VADJ_RX
J30 = JUMPER_1X2_100: Note: SHUNT 1-2; SILK: HSPC_PRSNT_M2C_L
R108 = Res_0201_100
Z_SH-J1 Z_SH-J3 Z_SH-J5 = SHUNT-HEADER_-_2POS
C168 C170 C179 = CAP_0603_10uF
C169 C171 C176 C181-C183 C186-C189 = CAP_0201_0.1uF: Mfr_Part_Number: CGB1T3X5R0J104M022BB
C172 C177 C190-C195 = CAP_0603_0.1uF
C173 C175 C180 = CAP_0603_1uF
C174 C178 = CAP_1206_100uF_6.3V
C184 C185 = CAP_0402_18pF
D7 = LED_GREEN_0: TI_SILKTEXT: VDDD33
FB12 FB13 = FERRITE_BEAD_0603_120_H
FB14 = FERRITE_BEAD_0603_26_H
J31 = USB_MINI_AB_MNE20-5G5P10: Mfr_Name: WURTH ELEKTRONIK; Mfr_Part_Number: 651305142821; TI_SILKTEXT: USB I/F
JP6 = JUMPER_1X3_100: Mfr_Part_Number: HTSW-103-07-G-S; Note: SHUNT 1-2; TI_Silktext: 3.3V_VDDD33
R109 = Res_0402_270
R110 R112 R113 R118-R121 R133-R137 R142 R147 = Res_0603_100_H: Mfr_Part_Number: ERJ-2RKF1000X
R111 = Res_0603_Zero
R116 R117 = Res_0603_10
R122 = Res_0603_12k
R130 = Res_0603_1k_H
R131 = Res_0603_2.2k
R178 = Res_0603_100_H: Mfr_Part_Number: ERJ-2RKF1000X_DNI; Note: DNI
TP7 = PROBE_POINT_0: TI_Silktext: 3P3USB
TP10 = PROBE_POINT_0: TI_Silktext: 1P8USB
TP36 = TESTPOINT_GRN: TI_SILKTEXT: LMK04828_CSb
U6 = TLV702: Mfr_Part_Number: TLV70233DBVT
U7 = SN74LVC1G125DBVR: Mfr_Name: Texas Instruments
U8 = FT4232HQ
U9 = EEPROM_93LC46B: Mfr_Part_Number: 93LC46B-I/MS
Y2 = CRYSTAL_ABM3_0
Z_SH-H2 = SHUNT-HEADER_-_3POS: Mfr_Part_Number: 1-382811-6
JP7 JP9 = JUMPER_1X2_100: Note: SHUNT 1-2; SILK: ?????
JP8 = JUMPER_1X2_100: Mfr_Part_Number: HTSW-102-07-G-S_DNI; Note: DNI; SILK: ?????
R138-R141 R143-R146 = Res_0603_1k_H: Mfr_Part_Number: ERJ-2RKF1001X
U10-U12 = SN74AVC4T774: Mfr_Name: Texas Instruments

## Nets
+3.3V_LMX: C100.1 C101.1 C102.2 C103.1 C106.1 C107.2 C113.1 C114.2 R46.2 U3.7(VccDIG) U3.11(VccCP) U3.15(VccDIV) U3.21(VccBUF) U3.26(VccDBLR) U3.37(VccVCO) ; also on sheet 14
+3.3V_LMXRF: C99.1 C105.1 R44.2 R45.2 R48.2 R49.2 ; also on sheet 14
+3.3VCLK: FB1.2 FB2.1 FB3.1 FB4.1 FB5.1 FB6.1 FB10.1 FB11.1 R82.1 R88.1 R96.2 SJP1.3(Pin3) ; also on sheet 14
GND: C1.2 C2.2 C3.1 C4.1 C14.1 C24.1 C41.2 C42.2 C43.2 C54.2 C55.2 C56.2 C57.2 C58.2 C59.2 C60.2 C61.2 C62.2 C63.2 C64.2 C65.2 C66.2 C67.2 C68.2 C69.2 C70.2 C71.2 C72.2 C73.2 C74.2 C75.2 C76.2 C77.2 C78.2 C79.2 C80.2 C81.2 C82.2 C83.2 C84.2 C85.2 C86.2 C87.2 C88.2 C89.2 C90.2 C91.2 C92.2 C93.2 C94.2 C95.2 C96.2 C99.2 C100.2 C101.2 C102.1 C103.2 C104.1 C105.2 C106.2 C107.1 C109.2 C111.1 C112.1 C113.2 C114.1 C115.1 C116.1 C117.1 C118.1 C119.2 C121.2 C122.2 C130.2 C132.2 C137.1 C138.1 C139.1 C140.1 C141.1 C146.1 C152.1 C154.1 C155.1 C156.1 C157.2 C158.2 C159.2 C160.1 C161.1 C162.1 C163.2 C164.2 C165.2 C166.2 C167.1 C168.2 C169.2 C170.2 C171.2 C172.2 C173.2 C174.2 C175.2 C176.2 C177.2 C178.2 C179.2 C180.2 C181.2 C182.2 C183.2 C184.2 C185.2 C186.2 C187.2 C188.2 C189.2 C190.2 C191.2 C192.2 C193.2 C194.2 C195.2 D2.2(CATHODE) D3.2(CATHODE) D4.2(CATHODE) D5.2(CATHODE) D6.2(CATHODE) J1.2(SHIELD1) J1.3(SHIELD2) J1.4(SHIELD3) J1.5(SHIELD4) J2.2(GND) J2.3(GND) J2.4(GND) J2.5(GND) J3.2(SHIELD1) J3.3(SHIELD2) J3.4(SHIELD3) J3.5(SHIELD4) J4.2(SHIELD1) J4.3(SHIELD2) J4.4(SHIELD3) J4.5(SHIELD4) J5.2(GND) J5.3(GND) J5.4(GND) J5.5(GND) J6.2(SHIELD1) J6.3(SHIELD2) J6.4(SHIELD3) J6.5(SHIELD4) J14.2(GND) J14.3(GND) J14.4(GND) J14.5(GND) J15.2(GND) J15.3(GND) J15.4(GND) J15.5(GND) J18.2(GND) J18.3(GND) J18.4(GND) J18.5(GND) J20.2(SHIELD1) J22.2(GND) J22.3(GND) J22.4(GND) J22.5(GND) J23.2(SHIELD1) J23.3(SHIELD2) J23.4(SHIELD3) J23.5(SHIELD4) J24.2(SHIELD1) J24.3(SHIELD2) J24.4(SHIELD3) J24.5(SHIELD4) J25.A1 J25.A4 J25.A5 J25.A8 J25.A9 J25.A12 J25.A13 J25.A16 J25.A17 J25.A20 J25.A24 J25.A25 J25.A28 J25.A29 J25.A32 J25.A33 J25.A36 J25.A37 J25.A40 J25.B3 J25.B6 J25.B7 J25.B10 J25.B11 J25.B14 J25.B15 J25.B18 J25.B26 J25.B27 J25.B30 J25.B31 J25.B34 J25.B35 J25.B38 J25.B39 J25.C5 J25.C8 J25.C24 J25.C25 J25.C28 J25.C29 J25.C32 J25.C33 J25.C36 J25.C38 J25.C40 J25.D3 J25.D6 J25.D25 J25.D28 J25.D37 J25.D39 J25.E26 J25.E29 J25.E32 J25.E35 J25.E38 J25.E40 J25.F27 J25.F30 J25.F33 J25.F36 J25.F39 J25.G5 J25.G8 J25.G11 J25.G14 J25.G26 J25.G29 J25.G32 J25.G35 J25.G38 J25.G40 J25.H27 J25.H30 J25.H33 J25.H36 J25.H39 J25.J29 J25.J32 J25.J35 J25.J38 J25.J40 J25.K30 J25.K33 J25.K36 J25.K39 J25.L30 J25.L31 J25.L34 J25.L35 J25.L38 J25.L39 J25.M1 J25.M29 J25.M32 J25.M33 J25.M36 J25.M37 J25.M40 J25.Y4 J25.Y5 J25.Y8 J25.Y9 J25.Y12 J25.Y13 J25.Y16 J25.Y17 J25.Y20 J25.Y21 J25.Y24 J25.Y25 J25.Y28 J25.Y29 J25.Y32 J25.Y33 J25.Y36 J25.Y37 J25.Y40 J25.Z2 J25.Z3 J25.Z7 J25.Z10 J25.Z11 J25.Z14 J25.Z15 J25.Z18 J25.Z19 J25.Z22 J25.Z23 J25.Z26 J25.Z27 J25.Z30 J25.Z31 J25.Z34 J25.Z35 J25.Z38 J25.Z39 J28.3 J31.5(GND) J31.6(GND1) J31.7(GND2) J31.8(GND3) J31.9(GND4) J38.2(GND) J38.3(GND) J38.4(GND) J38.5(GND) JP5.1 JP7.2 JP8.2 JP9.2 R11.2 R12.2 R17.2 R18.2 R21.2 R23.2 R26.2 R31.2 R32.2 R33.2 R51.1 R52.1 R53.1 R56.2 R57.2 R58.2 R61.2 R62.2 R63.2 R64.2 R65.2 R66.2 R68.2 R71.2 R72.2 R74.2 R75.2 R78.2 R79.2 R80.2 R81.2 R84.2 R85.2 R86.2 R87.2 R89.2 R90.2 R92.2 R93.2 R94.2 R95.2 R99.2 R106.2 R108.2 R109.2 R122.1 R184.2 R185.2 R187.2 R188.2 R189.2 SJP1.1(Pin1) T1.2(secondary_ct) T1.4(primary) T2.4(primary) U1.A1(AGND) U1.A2(AGND) U1.A3(AGND) U1.A6(AGND) U1.A7(AGND) U1.A12(DGND) U1.B2(AGND) U1.B3(AGND) U1.B4(AGND) U1.B5(AGND) U1.B6(AGND) U1.B7(AGND) U1.B12(DGND) U1.C6(AGND) U1.D1(AGND) U1.D6(AGND) U1.D9(DGND) U1.D10(DGND) U1.E1(AGND) U1.E6(AGND) U1.F2(AGND) U1.F3(AGND) U1.F6(AGND) U1.F9(DGND) U1.F10(DGND) U1.G2(AGND) U1.G3(AGND) U1.G6(AGND) U1.G9(DGND) U1.G10(DGND) U1.H1(AGND) U1.H6(AGND) U1.J1(AGND) U1.J6(AGND) U1.J9(DGND) U1.J10(DGND) U1.L2(AGND) U1.L3(AGND) U1.L4(AGND) U1.L5(AGND) U1.L6(AGND) U1.L7(AGND) U1.L12(DGND) U1.M1(AGND) U1.M2(AGND) U1.M3(AGND) U1.M6(AGND) U1.M7(AGND) U1.M12(DGND) U2.8(GND) U2.9(A0) U2.15(PWRPAD) U3.2(GND) U3.4(GND) U3.6(GND) U3.13(GND) U3.14(GND) U3.25(GND) U3.31(GND) U3.34(GND) U3.39(GND) U3.40(NC4) U3.41(PWRPAD) U4.65(DAP) U5.3(A2) U5.4(VSS) U6.2(GND) U7.3(GND) U8.1(GND) U8.5(GND) U8.10(AGND) U8.11(GND) U8.13(TEST) U8.15(GND) U8.25(GND) U8.35(GND) U8.47(GND) U8.51(GND) U8.65(PWRPAD) U9.5(VSS) U10.7(DIR3) U10.10(GND) U11.10(GND) U12.1(DIR1) U12.2(DIR2) U12.7(DIR3) U12.8(DIR4) U12.10(GND) U15.4(V-) Y1.3(GND) ; also on sheet 13 14
VBUS: C175.1 R111.1 U6.1(IN) U6.3(EN)
VBUSS: C173.1 FB14.1 U6.5(OUT)
VCCIN: C104.2 U3.10(VccIN)
VDDD33: C1.1 C2.1 C41.1 C42.1 C43.1 C172.1 C180.1 C186.1 C187.1 C188.1 C189.1 C190.1 C192.1 C194.1 D1.1(ANODE) D7.1(ANODE) FB12.1 FB13.1 JP6.1(Pin1) R27.1 R28.1 R29.1 R30.1 R39.1 R41.1 R114.1 R115.1 R123.1 R124.1 R125.1 R130.1 U2.2(VDD) U7.5(VCC) U8.20(VCCIO) U8.31(VCCIO) U8.42(VCCIO) U8.56(VCCIO) U9.8(VCC) U10.1(DIR1) U10.2(DIR2) U10.8(DIR4) U10.16(VCCA) U11.1(DIR1) U11.2(DIR2) U11.7(DIR3) U11.8(DIR4) U11.16(VCCA) U12.16(VCCA) U15.8(V+) ; also on sheet 14
VDDL19: C191.1 C193.1 C195.1 R132.1 U10.15(VCCB) U11.15(VCCB) U12.15(VCCB) ; also on sheet 13
VINA: BALUN1.1(IN) J2.1(CENTER)
VINB: BALUN2.1(IN) J5.1(CENTER)
1P8V_USB: C178.1 C179.1 C181.1 C182.1 C183.1 TP10.1 U8.12(VCORE) U8.37(VCORE) U8.49(VREGOUT) U8.64(VCORE)
3P3USB: C170.1 C171.1 FB13.2 TP7.1 U8.9(VPLL)
3P3V_RX: R105.2 TP5.1
3P3VAUX: C167.2 J25.D32 J28.4 U5.8(VCC)
12P0V_RX: J25.C35 J25.C37
ADBUS0: U8.16(ADBUS0) U10.3(A1)
ADBUS1: U8.17(ADBUS1) U10.4(A2)
ADBUS2: U8.18(ADBUS2) U10.5(A3)
ADBUS3: U8.19(ADBUS3) U10.6(A4)
ADC_CLK: R133.2 U1.F8(SCLK)
ADC_SCSb: R136.2 U1.E8(\\~{SCS})
ADC_SDI: R134.2 U1.G8(SDI)
ADC_SDO: R135.2 U1.H8(SDO)
BDBUS0: R112.1 U8.26(BDBUS0)
BDBUS1: U7.2(A) U8.27(BDBUS1)
BDBUS2: R113.1 U8.28(BDBUS2)
BDBUS3: U7.1(~{OE}) U8.29(BDBUS3)
CALTRG: J9.2 R23.1 U1.E7(CALTRG)
CDBUS0: R118.1 U8.38(CDBUS0)
CDBUS1: R119.1 U8.39(CDBUS1)
CDBUS2: R115.2 R120.1 U8.40(CDBUS2)
CDBUS3: R114.2 R121.1 U8.41(CDBUS3)
CE: JP5.2 R46.1 U3.1(CE)
CLK+: C49.1 R43.2 T2.1(secondary_dot)
CLK-: C52.1 R43.1 T2.3(secondary)
CLK-IN: R67.1 R69.1 R70.2 R72.1 T1.6(primary_dot)
CLK_+: C48.2 C49.2 C50.2 U1.F1(CLK+)
CLK_-: C51.2 C52.2 C53.2 U1.G1(CLK-)
CLKIN0: J38.1(CENTER) R186.1 R187.1
CLKIN0_N: C24.2 U4.38(CLKIN0n)
CLKIN0_P: C20.2 U4.37(CLKIN0p)
CLKIN1: C20.1 R186.2
CLKIN1_N: C136.2 C137.2 U4.35(CLKIN1n/FBCLKINn/FINn)
CLKIN1_P: C134.2 U4.34(CLKIN1p/FBCLKINp/FINp)
CLKINN: C136.1 R73.2 T1.3(secondary)
CLKINP: C134.1 R68.1 R69.2 R73.1 T1.1(secondary_dot)
CLKLA_0N: R90.1 R127.1 U4.63(DCLKOUT12n)
CLKLA_0P: R89.1 R126.1 U4.62(DCLKOUT12p)
CLKM: C53.1 C135.2
CLKP: C48.1 C133.2
CP1: C128.1 C130.1 U4.32(CPOUT1) Y1.1(VC)
CP2: C131.1 C132.1 U4.46(CPOUT2)
CPout: C119.1 C120.1 R54.1 U3.12(CPout)
DA0+: C5.1 U1.E12(DA0+)
DA0-: C6.1 U1.F12(DA0-)
DA0_M: C6.2 J25.A11
DA0_P: C5.2 J25.A10
DA1+: C7.1 U1.C12(DA1+)
DA1-: C8.1 U1.D12(DA1-)
DA1_M: C8.2 J25.C7
DA1_P: C7.2 J25.C6
DA2+: C9.1 U1.A10(DA2+)
DA2-: C10.1 U1.A11(DA2-)
DA2_M: C10.2 J25.A7
DA2_P: C9.2 J25.A6
DA3+: C11.1 U1.A8(DA3+)
DA3-: C12.1 U1.A9(DA3-)
DA3_M: C12.2 J25.A3
DA3_P: C11.2 J25.A2
DA4+: C13.1 U1.E11(DA4+)
DA4-: C15.1 U1.F11(DA4-)
DA4_M: C15.2 J25.Y15
DA4_P: C13.2 J25.Y14
DA5+: C16.1 U1.C11(DA5+)
DA5-: C18.1 U1.D11(DA5-)
DA5_M: C18.2 J25.Y11
DA5_P: C16.2 J25.Y10
DA6+: C19.1 U1.B10(DA6+)
DA6-: C21.1 U1.B11(DA6-)
DA6_M: C21.2 J25.B9
DA6_P: C19.2 J25.B8
DA7+: C22.1 U1.B8(DA7+)
DA7-: C23.1 U1.B9(DA7-)
DA7_M: C23.2 J25.B5
DA7_P: C22.2 J25.B4
DB0+: C25.1 U1.H12(DB0+)
DB0-: C26.1 U1.G12(DB0-)
DB0_M: C26.2 J25.B12
DB0_P: C25.2 J25.B13
DB1+: C27.1 U1.K12(DB1+)
DB1-: C28.1 U1.J12(DB1-)
DB1_M: C28.2 J25.A14
DB1_P: C27.2 J25.A15
DB2+: C29.1 U1.M10(DB2+)
DB2-: C30.1 U1.M11(DB2-)
DB2_M: C30.2 J25.B16
DB2_P: C29.2 J25.B17
DB3+: C31.1 U1.M8(DB3+)
DB3-: C32.1 U1.M9(DB3-)
DB3_M: C32.2 J25.A18
DB3_P: C31.2 J25.A19
DB4+: C33.1 U1.H11(DB4+)
DB4-: C34.1 U1.G11(DB4-)
DB4_M: C34.2 J25.Z12
DB4_P: C33.2 J25.Z13
DB5+: C35.1 U1.K11(DB5+)
DB5-: C36.1 U1.J11(DB5-)
DB5_M: C36.2 J25.Z16
DB5_P: C35.2 J25.Z17
DB6+: C37.1 U1.L10(DB6+)
DB6-: C38.1 U1.L11(DB6-)
DB6_M: C38.2 J25.Y18
DB6_P: C37.2 J25.Y19
DB7+: C39.1 U1.L8(DB7+)
DB7-: C40.1 U1.L9(DB7-)
DB7_M: C40.2 J25.Y22
DB7_P: C39.2 J25.Y23
DCLKOUT2_N: C135.1 R75.1 U4.16(DCLKOUT2n)
DCLKOUT2_P: C133.1 R74.1 U4.15(DCLKOUT2p)
DCLKOUT6_N: C153.1 R95.1 U4.28(DCLKOUT6n)
DCLKOUT6_P: C151.1 R94.1 U4.27(DCLKOUT6p)
DCLKOUT8_N: R24.1 R57.1 U4.52(DCLKOUT8n)
DCLKOUT8_P: R22.1 R58.1 U4.51(DCLKOUT8p)
DCLKOUT10_N: C143.2 J24.1(CENTER)
DCLKOUT10_P: C142.2 J23.1(CENTER)
DCLKOUT10N: C143.1 R87.1 U4.55(DCLKOUT10n)
DCLKOUT10P: C142.1 R86.1 U4.54(DCLKOUT10p)
DDBUS0: U8.48(DDBUS0) U11.3(A1)
DDBUS1: U8.52(DDBUS1) U11.4(A2)
DDBUS2: U8.53(DDBUS2) U11.5(A3)
DDBUS3: U8.54(DDBUS3) U11.6(A4)
DDBUS4: U8.55(DDBUS4) U12.3(A1)
DDBUS5: U8.57(DDBUS5) U12.4(A2)
DDBUS6: U8.58(DDBUS6) U12.5(A3)
DDBUS7: U8.59(DDBUS7) U12.6(A4)
DEVCLKIN: J18.1(CENTER) T2.6(primary_dot)
DM: R116.2 U8.7(DM)
DP: R117.2 U8.8(DP)
EE_ADDR0_RX: J25.C34 U5.1(A0)
EE_ADDR1_RX: J25.D35 U5.2(A1)
EECLK: R124.2 U8.62(EECLK) U9.2(CLK)
EECS: R125.2 U8.63(EECS) U9.1(CS)
EEDATA: R131.1 U8.61(EEDATA) U9.3(DI)
FMC_SCL: J25.C30 J28.2 U5.6(SCL)
FMC_SDA: J25.C31 J28.1 U5.5(SDA)
FPGA_JESD_CLK_A_N: J25.D5 R129.2
FPGA_JESD_CLK_A_P: J25.D4 R128.2
FPGA_JESD_CLK_B_N: J25.G7 R127.2
FPGA_JESD_CLK_B_P: J25.G6 R126.2
FPGA_JESD_CLK_C_N: J25.Z21 R24.2
FPGA_JESD_CLK_C_P: J25.Z20 R22.2
FPGA_JESD_SYSREFM: J25.G10 R60.2
FPGA_JESD_SYSREFP: J25.G9 R59.2
GTXCLKM: R64.1 R129.1 U4.2(DCLKOUT0n)
GTXCLKP: R65.1 R128.1 U4.1(DCLKOUT0p)
HSPC_PRSNT_M2C_L: J25.Z1 J30.1
INA+: BALUN1.3(O1) R1.1
INA-: BALUN1.2(O2) R4.1
INA_+: J1.1(CENTER) R180.1
INA_-: J3.1(CENTER) R179.1
INAN: R4.2 R179.2 U1.A5(INA-)
INAP: R1.2 R180.2 U1.A4(INA+)
INB+: BALUN2.2(O2) R6.1
INB-: BALUN2.3(O1) R9.1
INB_+: J4.1(CENTER) R151.1
INB_-: J6.1(CENTER) R162.1
INBN: R9.2 R162.2 U1.M5(INB-)
INBP: R6.2 R151.2 U1.M4(INB+)
JESD_SYSREFM: R60.1 R61.1 U4.4(SDCLKOUT1n)
JESD_SYSREFP: R59.1 R62.1 U4.3(SDCLKOUT1p)
LM95233_SMBCLK: R41.2 R112.2 U2.13(SMBCLK)
LM95233_SMBDAT: R39.2 R110.2 R113.2 U2.12(SMBDAT)
LMK04828_CSb: R120.2 TP36.1(TP) U4.18(\\~{CS})
LMK04828_SYNC: J25.J15 R97.2
LMK LOCKED: D5.1(ANODE) R102.1
LMK_CLKIN: J22.1(CENTER) R70.1 R71.1
LMK_LMX_CLK: R118.2 U3.16(SCK) U4.19(SCK)
LMK_LMX_DATA: R119.2 U3.17(SDI) U4.20(SDIO)
LMK_SDO: R99.1 R178.2 U4.5(RESET)
LMX_CLKB: C108.2 R52.2 R67.2
LMX_CLKM: C51.1 R45.1 U3.22(RFoutAM)
LMX_CLKP: C50.1 R44.1 U3.23(RFoutAP)
LMX_CSb: R121.2 U3.24(CSB)
LMX_OSCM: C151.2 C249.1 U3.9(OSCinM)
LMX_OSCP: C153.2 C250.1 U3.8(OSCinP)
LMX_SDO: R47.2 U8.43(CDBUS4)
MUX_OUT: R47.1 R50.2 U3.20(MUXout)
NCOA0: J7.2 R11.1 R138.2 U1.C7(NCOA0)
NCOA1: J7.4 R12.1 R139.2 U1.D7(NCOA1)
NCOB0: J7.6 R17.1 R140.2 U1.K7(NCOB0)
NCOB1: J7.8 R18.1 R141.2 U1.J7(NCOB1)
OSC_M: C250.2 R188.1 U4.41(OSCOUTn)
OSC_P: C249.2 R189.1 U4.40(OSCOUTp)
OSCI: C184.1 U8.2(OSCI) Y2.2
OSCINN: C150.2 C152.2 U4.44(OSCINn)
OSCINP: C145.2 C146.2 U4.43(OSCINp)
OSCN: C149.2 C150.1 R88.2 R93.1
OSCO: C185.1 U8.3(OSCO) Y2.1
OSCP: C144.2 C145.1 R82.2 R85.1
OVRA0: D12.1(ANODE) J25.G27 R143.2 U1.C8(OVRA0)
OVRA1: R144.2 U1.D8(OVRA1)
OVRB0: D9.1(ANODE) J25.D26 R145.2 U1.K8(OVRB0)
OVRB1: R146.2 U1.J8(OVRB1)
PD: J8.2 R21.1 U1.K6(PD)
PG_RX1: J25.F1 J26.2 R104.2
PLL2 LOCKED: D6.1(ANODE) R103.1
PRSNT_M2C_L: J25.H2 R106.1
RFOUTB_M: C110.1 R49.1 U3.19(RFoutBM)
RFOUTB_P: C108.1 R48.1 U3.18(RFoutBP)
RFOUTBM: C110.2 J20.1(CENTER) R53.2
STAT 0: D3.1(ANODE) R100.1
STAT 1: D4.1(ANODE) R101.1
SYNC: R96.1 R97.1 R98.1 TP4.1(TP) U4.6(SYNC)
SYNC_N: J25.G13 R36.1
SYNC_P: J25.G12 R35.1
SYNC_SE: J25.H31 R25.1 R98.2
SYNCSE: R25.2 R26.1 U1.C2(SYNC~_SE)
SYS+: C45.2 U1.K1(SYSREF+)
SYS-: C47.2 U1.L1(SYSREF-)
SYSREF+: R76.1 R78.1 U4.13(SDCLKOUT3p)
SYSREF-: R77.1 R79.1 U4.14(SDCLKOUT3n)
SYSREFM: C47.1 R77.2 R80.1
SYSREFP: C45.1 R76.2 R81.1
TCRIT1: R28.2 R37.2 TP1.1(TP) U2.10(\\~{TCRIT}1)
TCRIT2: R27.2 TP2.1(TP) U2.11(\\~{TCRIT}2)
TCRIT3: R29.2 TP3.1(TP) U2.14(\\~{TCRIT}3)
TDI: J25.D30 J27.1
TDIODE+: J17.2 R40.2 U1.K2(TDIODE+)
TDIODE-: J17.1 R42.2 U1.K3(TDIODE-)
TDIODEN: C44.2 C46.2 Q1.2(E) R42.1 U2.5(D-)
TDIODEP: C44.1 R40.1 U2.7(D1+)
TDO: J25.D31 J27.2
TMSP+: J14.1(CENTER) R34.1
TMSP-: J15.1(CENTER) R38.1
TMSTP+: R34.2 R35.2 U1.B1(TMSTP+)
TMSTP-: R36.2 R38.2 U1.C1(TMSTP-)
V_BUS: C174.1 C177.1 FB14.2 JP6.3(Pin3)
VA11: C54.1 C55.1 C56.1 C57.1 C58.1 C59.1 C60.1 C61.1 C62.1 C63.1 C64.1 C65.1 C66.1 C67.1 C68.1 TP31.1 U1.C5(VA11) U1.D2(VA11) U1.D3(VA11) U1.D5(VA11) U1.E5(VA11) U1.F5(VA11) U1.G5(VA11) U1.H5(VA11) U1.J2(VA11) U1.J3(VA11) U1.J5(VA11) U1.K5(VA11) ; also on sheet 13
VA19: C69.1 C70.1 C71.1 C72.1 C73.1 C74.1 C75.1 C76.1 C77.1 C78.1 C79.1 C80.1 C81.1 C82.1 C83.1 R13.1 R14.1 R15.1 R16.1 R19.1 R20.1 TP32.1 U1.C4(VA19) U1.D4(VA19) U1.E2(VA19) U1.E3(VA19) U1.E4(VA19) U1.F4(VA19) U1.G4(VA19) U1.H2(VA19) U1.H3(VA19) U1.H4(VA19) U1.J4(VA19) U1.K4(VA19) ; also on sheet 13
VADJ_RX: J25.E39 J25.F40 J25.G39 J25.H40 R104.1 R107.1 TP6.1
VBIAS_VCO: C116.2 U3.3(VbiasVCO)
VBIASBANK: C109.1 C111.2 U3.27(VbiasBANK)
VD11: C84.1 C85.1 C86.1 C87.1 C88.1 C89.1 C90.1 C91.1 C92.1 C93.1 C94.1 C95.1 C96.1 TP33.1 U1.C9(VD11) U1.C10(VD11) U1.E9(VD11) U1.E10(VD11) U1.G7(VD11) U1.H7(VD11) U1.H9(VD11) U1.H10(VD11) U1.K9(VD11) U1.K10(VD11) ; also on sheet 13
VIO_B_M2C_RX: J25.J39 J25.K40 R107.2
VPHY: C168.1 C169.1 FB12.2 U8.4(VPHY)
VREF_VCO1: C112.2 U3.29(VrefVCO)
VREF_VCO2: C115.2 U3.36(VrefVCO)
VREG_VCO: C117.2 U3.38(VregVCO)
VREGIN: C176.1 JP6.2(Pin2) U8.50(VREGIN)
VTUNE: C122.1 R55.2 U3.35(Vtune)
Y1_N: R91.1 R92.1 Y1.4(OUT_N)
Y1_P: R83.1 R84.1 Y1.5(OUT_P)
YO1_N: C149.1 R91.2
YO1_P: C144.1 R83.2
N19884870: C138.2 C139.2 C140.2 C141.2 FB1.1 Y1.6(VDD)
N19884947: SJP1.2(Pin2) Y1.2(NC)
N19887754: FB8.2 U4.42(VCC8_OSCin)
N19887756: C160.2 C161.2 C162.2 FB6.2 FB7.1 FB8.1 FB9.1 U4.47(VCC10_PLL2)
N19887760: C165.1 FB10.2 U4.53(VCC11_CG3)
N19887762: C166.1 FB11.2 U4.64(VCC12_CG0)
N19887789: R102.2 U4.31(STATUS_LD1)
N19887795: R103.2 U4.48(STATUS_LD2)
N19887804: R101.2 U4.59(CLKin_SEL1)
N19887822: R100.2 U4.58(CLKin_SEL0)
N19887828: C163.1 U4.12(LDObyp2)
N19887830: C164.1 U4.11(LDObyp1)
N19887836: C154.2 C155.2 C156.2 FB2.2 U4.10(VCC1_VCO) U4.33(VCC5_DIG) U4.36(VCC6_PLL1)
N19887876: FB7.2 U4.39(VCC7_OSCout)
N19887878: FB9.2 U4.45(VCC9_CP2)
N19887910: C158.1 FB4.2 U4.21(VCC3_SYSREF)
N19887912: C157.1 FB3.2 U4.17(VCC2_CG1)
N19887930: C159.1 FB5.2 U4.26(VCC4_CG2)
N20234062: C118.2 U3.33(VbiasVARAC)
N20239082: R51.2 U3.30(Rext)
N20251064: C120.2 R56.1
N20251377: C121.1 R54.2 R55.1
N20258125: D2.1(ANODE) R50.1
N20381922: R130.2 U8.14(RESET)
N20381931: R122.2 U8.6(REF)
N20382558: R123.2 R131.2 U9.4(DO)
N20382827: J31.3(D+) R117.1
N20382847: J31.2(D-) R116.1
N20392160: J31.1(VBUS) R111.2
N20393078: D7.2(CATHODE) R109.1
N20442573: J7.1 R13.2
N20442576: J7.3 R14.2
N20442579: J7.5 R15.2
N20442582: J7.7 R16.2
N20446174: TP26.1(TP) U1.C3(BG)
N20447902: D1.2(CATHODE) R37.1
N20452911: C46.1 Q1.1(B) Q1.3(C) U2.6(D2+)
N20475697: R138.1 U11.14(B1)
N20475701: R139.1 U11.13(B2)
N20475713: R140.1 U11.12(B3)
N20475725: R141.1 U11.11(B4)
N20475883: R142.1 U11.9(OEb)
N20476138: JP8.1 R142.2
N20477206: R133.1 U10.14(B1)
N20477210: R134.1 U10.13(B2)
N20477222: R135.1 U10.12(B3)
N20477234: R132.2 R136.1 U10.11(B4)
N20477392: R137.1 U10.9(OEb)
N20477396: JP7.1 R137.2
N20478124: R110.1 U7.4(Y)
N20479286: R143.1 U12.14(B1)
N20479288: R144.1 U12.13(B2)
N20479290: R145.1 U12.12(B3)
N20479292: R146.1 U12.11(B4)
N20479340: R147.1 U12.9(OEb)
N20479396: JP9.1 R147.2
N20523656: TP25.1(TP) U1.F7(CALSTAT)
N20560674: J25.C39 J25.D36 J25.D38 J25.D40 R105.1
N20560927: J25.D1 J26.1
N20597236: J30.2 R108.1
N20601243: D10.1(ANODE) U15.7(OUTB)
N20601382: D11.1(ANODE) U15.1(OUTA)
N20601403: D10.2(CATHODE) R185.1
N20601859: D11.2(CATHODE) R32.1
N20602433: C14.2 D9.2(CATHODE) R184.1 U15.5(INB+)
N20603216: C3.2 D12.2(CATHODE) R31.1 U15.3(INA+)
N20603624: C4.2 R30.2 R33.1 U15.2(INA-) U15.6(INB-)
N20606076: J9.1 R20.2
N20606250: J8.1 R19.2
N20733419: R178.1 U8.44(CDBUS5)
N20790993: C131.2 R66.1
N20790994: C128.2 R63.1

Not connected (* = marked no-connect by the designer): J25 A21 A22 A23 A26 A27 A30 A31 A34 A35 A38 A39 B1 B2 B19 B20* B21* B22 B23 B24 B25 B28 B29 B32 B33 B36 B37 B40 C1 C2 C3 C4 C9 C10 C11 C12 C13 C14 C15 C16 C17 C18 C19 C20 C21 C22* C23* C26* C27* D2 D7 D8* D9* D10 D11 D12 D13 D14 D15 D16 D17 D18 D19 D20* D21* D22 D23 D24* D27 D29* D33* D34 E1 E2 E3 E4 E5 E6 E7 E8 E9 E10 E11 E12 E13 E14 E15 E16 E17 E18 E19 E20 E21 E22 E23 E24 E25 E27 E28 E30 E31 E33 E34 E36 E37 F2 F3 F4 F5 F6 F7 F8 F9 F10 F11 F12 F13 F14 F15 F16 F17 F18 F19 F20 F21 F22 F23 F24 F25 F26 F28 F29 F31 F32 F34 F35 F37 F38 G1 G2 G3 G4 G15 G16 G17 G18 G19 G20 G21 G22 G23 G24 G25 G28 G30 G31 G33 G34 G36 G37 H1 H3 H4 H5 H6 H7 H8 H9 H10 H11 H12 H13 H14 H15 H16 H17 H18 H19 H20 H21 H22 H23 H24 H25 H26 H28 H29 H32 H34 H35 H37 H38 J1 J2 J3 J4 J5 J6 J7 J8 J9 J10 J11 J12 J13 J14 J16 J17 J18 J19 J20 J21 J22 J23 J24 J25 J26 J27 J28 J30 J31 J33 J34 J36 J37 K1 K2 K3 K4 K5 K6 K7 K8 K9 K10 K11 K12 K13 K14 K15 K16 K17 K18 K19 K20 K21 K22 K23 K24 K25 K26 K27 K28 K29 K31 K32 K34 K35 K37 K38 L1 L2 L3 L4 L5 L6 L7 L8 L9 L10 L11 L12 L13 L14 L15 L16 L17 L18 L19 L20 L21 L22 L23 L24 L25 L26 L27 L28 L29 L32 L33 L36 L37 L40 M2 M3 M4 M5 M6 M7 M8 M9 M10 M11 M12 M13 M14 M15 M16 M17 M18 M19 M20 M21 M22 M23 M24 M25 M26 M27 M28 M30 M31 M34 M35 M38 M39 Y1 Y2 Y3 Y6 Y7 Y26 Y27 Y30 Y31 Y34 Y35 Y38 Y39 Z4 Z5 Z6 Z8 Z9 Z24 Z25 Z28 Z29 Z32 Z33 Z36 Z37 Z40; J31 4(ID)*; T2 2(NOTUSED)*; U3 5(NC1)* 28(NC2)* 32(NC3)*; U4 7(NC1)* 8(NC2)* 9(NC3)* 22(SDCLKOUT5p)* 23(SDCLKOUT5n)* 24(DCLKOUT4p)* 25(DCLKOUT4n)* 29(SDCLKOUT7p)* 30(SDCLKOUT7n)* 49(SDCLKOUT9p)* 50(SDCLKOUT9n)* 56(SDCLKOUT11p)* 57(SDCLKOUT11n)* 60(SDCLKOUT13p)* 61(SDCLKOUT13n)*; U8 21(ADBUS4)* 22(ADBUS5)* 23(ADBUS6)* 24(ADBUS7)* 30(BDBUS4)* 32(BDBUS5)* 33(BDBUS6)* 34(BDBUS7)* 36(SUSPEND)* 45(CDBUS6)* 46(CDBUS7)* 60(PWREN)*; U9 6(ORG)*

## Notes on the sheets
sheet 1
- POWER
- USB
- SUPPLIES
- LEVEL SHIFTERS
- PAGES 13, 14
- PAGES  11, 12
- SPI
- JESD204B DATA
- FMC
- ANALOG INPUT
    CHANNEL A
- ADC08DJ2700
- CONNECTOR
- ADC08DJ3200
- SYNCB
- PAGE 2
- ADC12DJ1600
- PAGES 8, 9, 10
- ADC12DJ2700
- SPI
- ANALOG INPUT
    CHANNEL B
- ADC12DJ3200
- PAGES 2, 3, 4
- PAGE 2
- CLK
- SYSREF
- SPI
- SYSREF
- EXT CLK
- LMK04828
- PAGES 6, 7
- LMKCLK
- LMXCLK
- LMX2582
- PAGE 5
- 12500 TI Boulevard. Dallas, Texas 75243
- Engineer:
- J BRINKHURST  10/2015
- PCB:
- JV SMITH  10/2015
sheet 2
- R1 & R180 share a pad.
- Only the P and M's need to match.
- R4 & R179 share a pad.
- R6 & R151 share a pad.
- R9 & R162 share a pad.
- 12500 TI Boulevard. Dallas, Texas 75243
sheet 3
- R34 & R35 Share a pad.
- R36 & R38 share a pad.
- C48, C49, C50 share a pad.
- C51, C52, C53 share a pad.
- 12500 TI Boulevard. Dallas, Texas 75243
sheet 5
- RFOUTBP
- 12500 TI Boulevard. Dallas, Texas 75243
sheet 6
- FPGA_JESD*
- MUST MATCH LENGTH.
- Place near Vc pin of Y1
  R20 and C31 form voltage divider
  set the center frequency voltage for PLL2 reference
- Place close to U4
- FPGA_JESD*
- MUST MATCH LENGTH.
- Place close to LMK
- Place close to LMK
- MATCHED LENGTH
- Shared Pad
- Place close to LMK
- FPGA_JESD*
- MUST MATCH LENGTH.
- Y1 CMOS version OUTPUT on PIN 4
- Shared Pad
- Shared Pad
sheet 7
- Make sure this line does not hold LMK high
  before LMK can be programmed for SDO
